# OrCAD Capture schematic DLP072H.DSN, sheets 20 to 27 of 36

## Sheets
20 PAGE25 - RS-232, SSP, USB: size A3
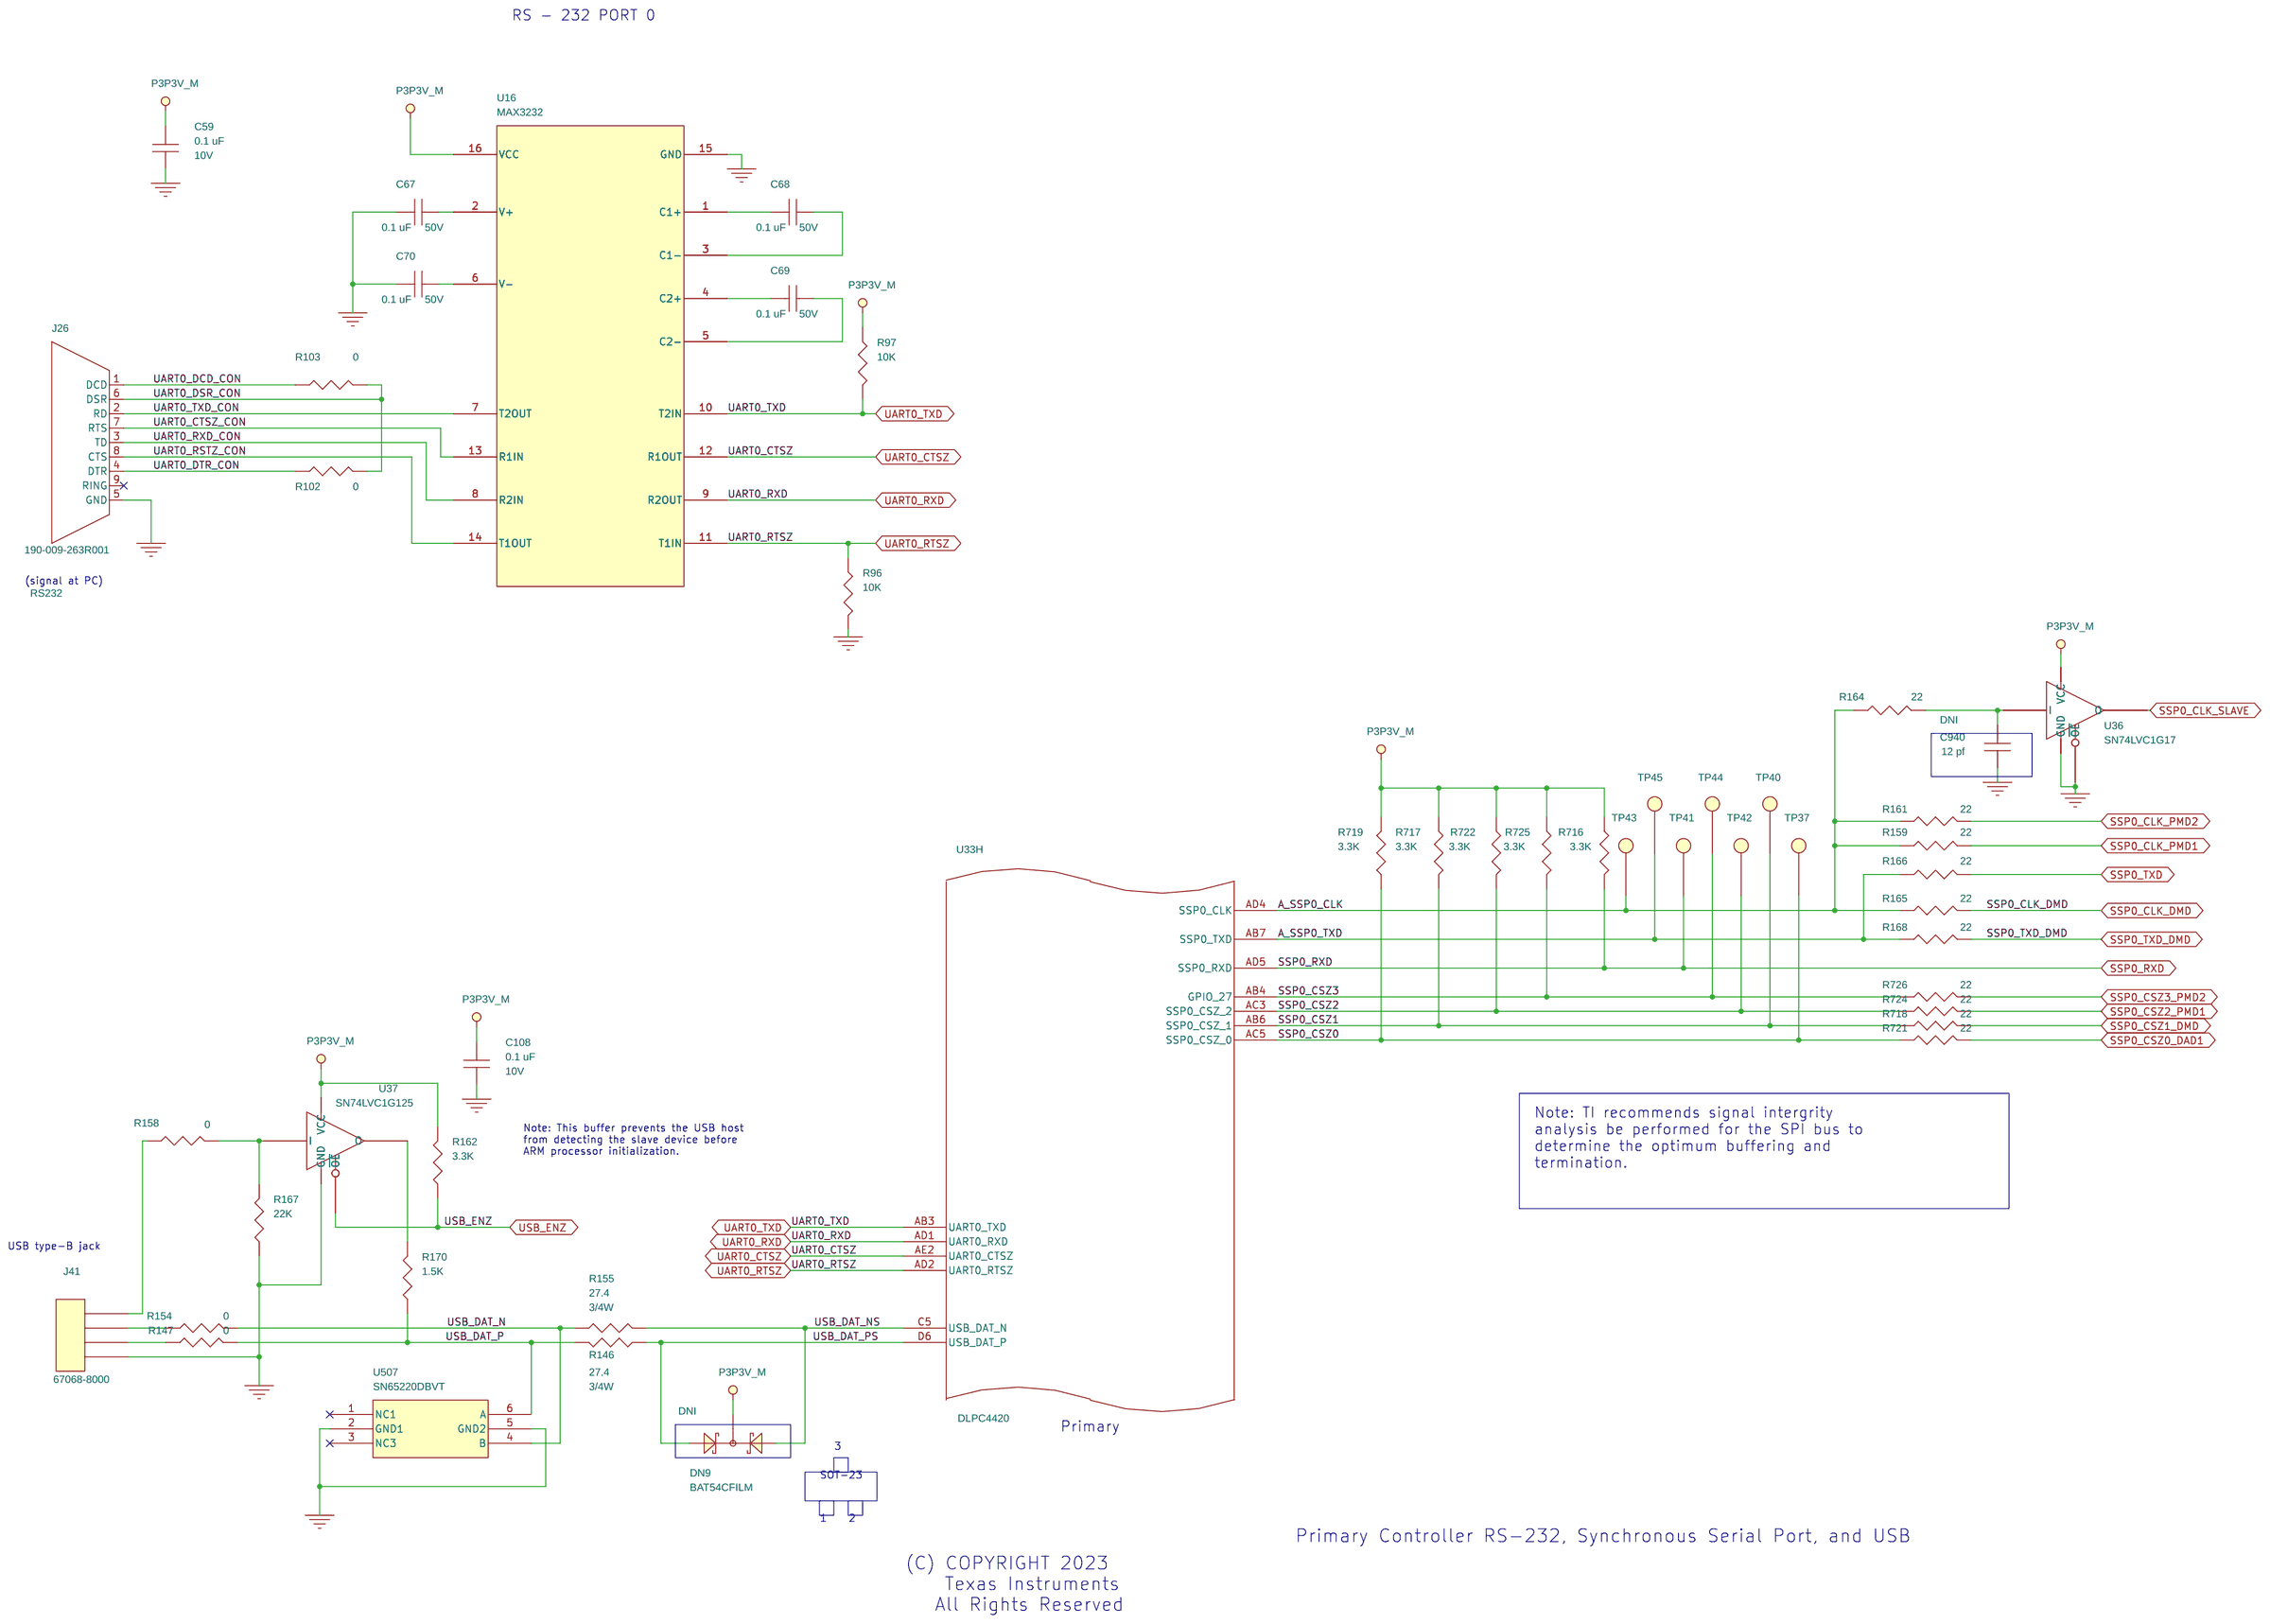
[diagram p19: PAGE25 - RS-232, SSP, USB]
21 PAGE26 - FLASH & SRAM MEMORY: size A3
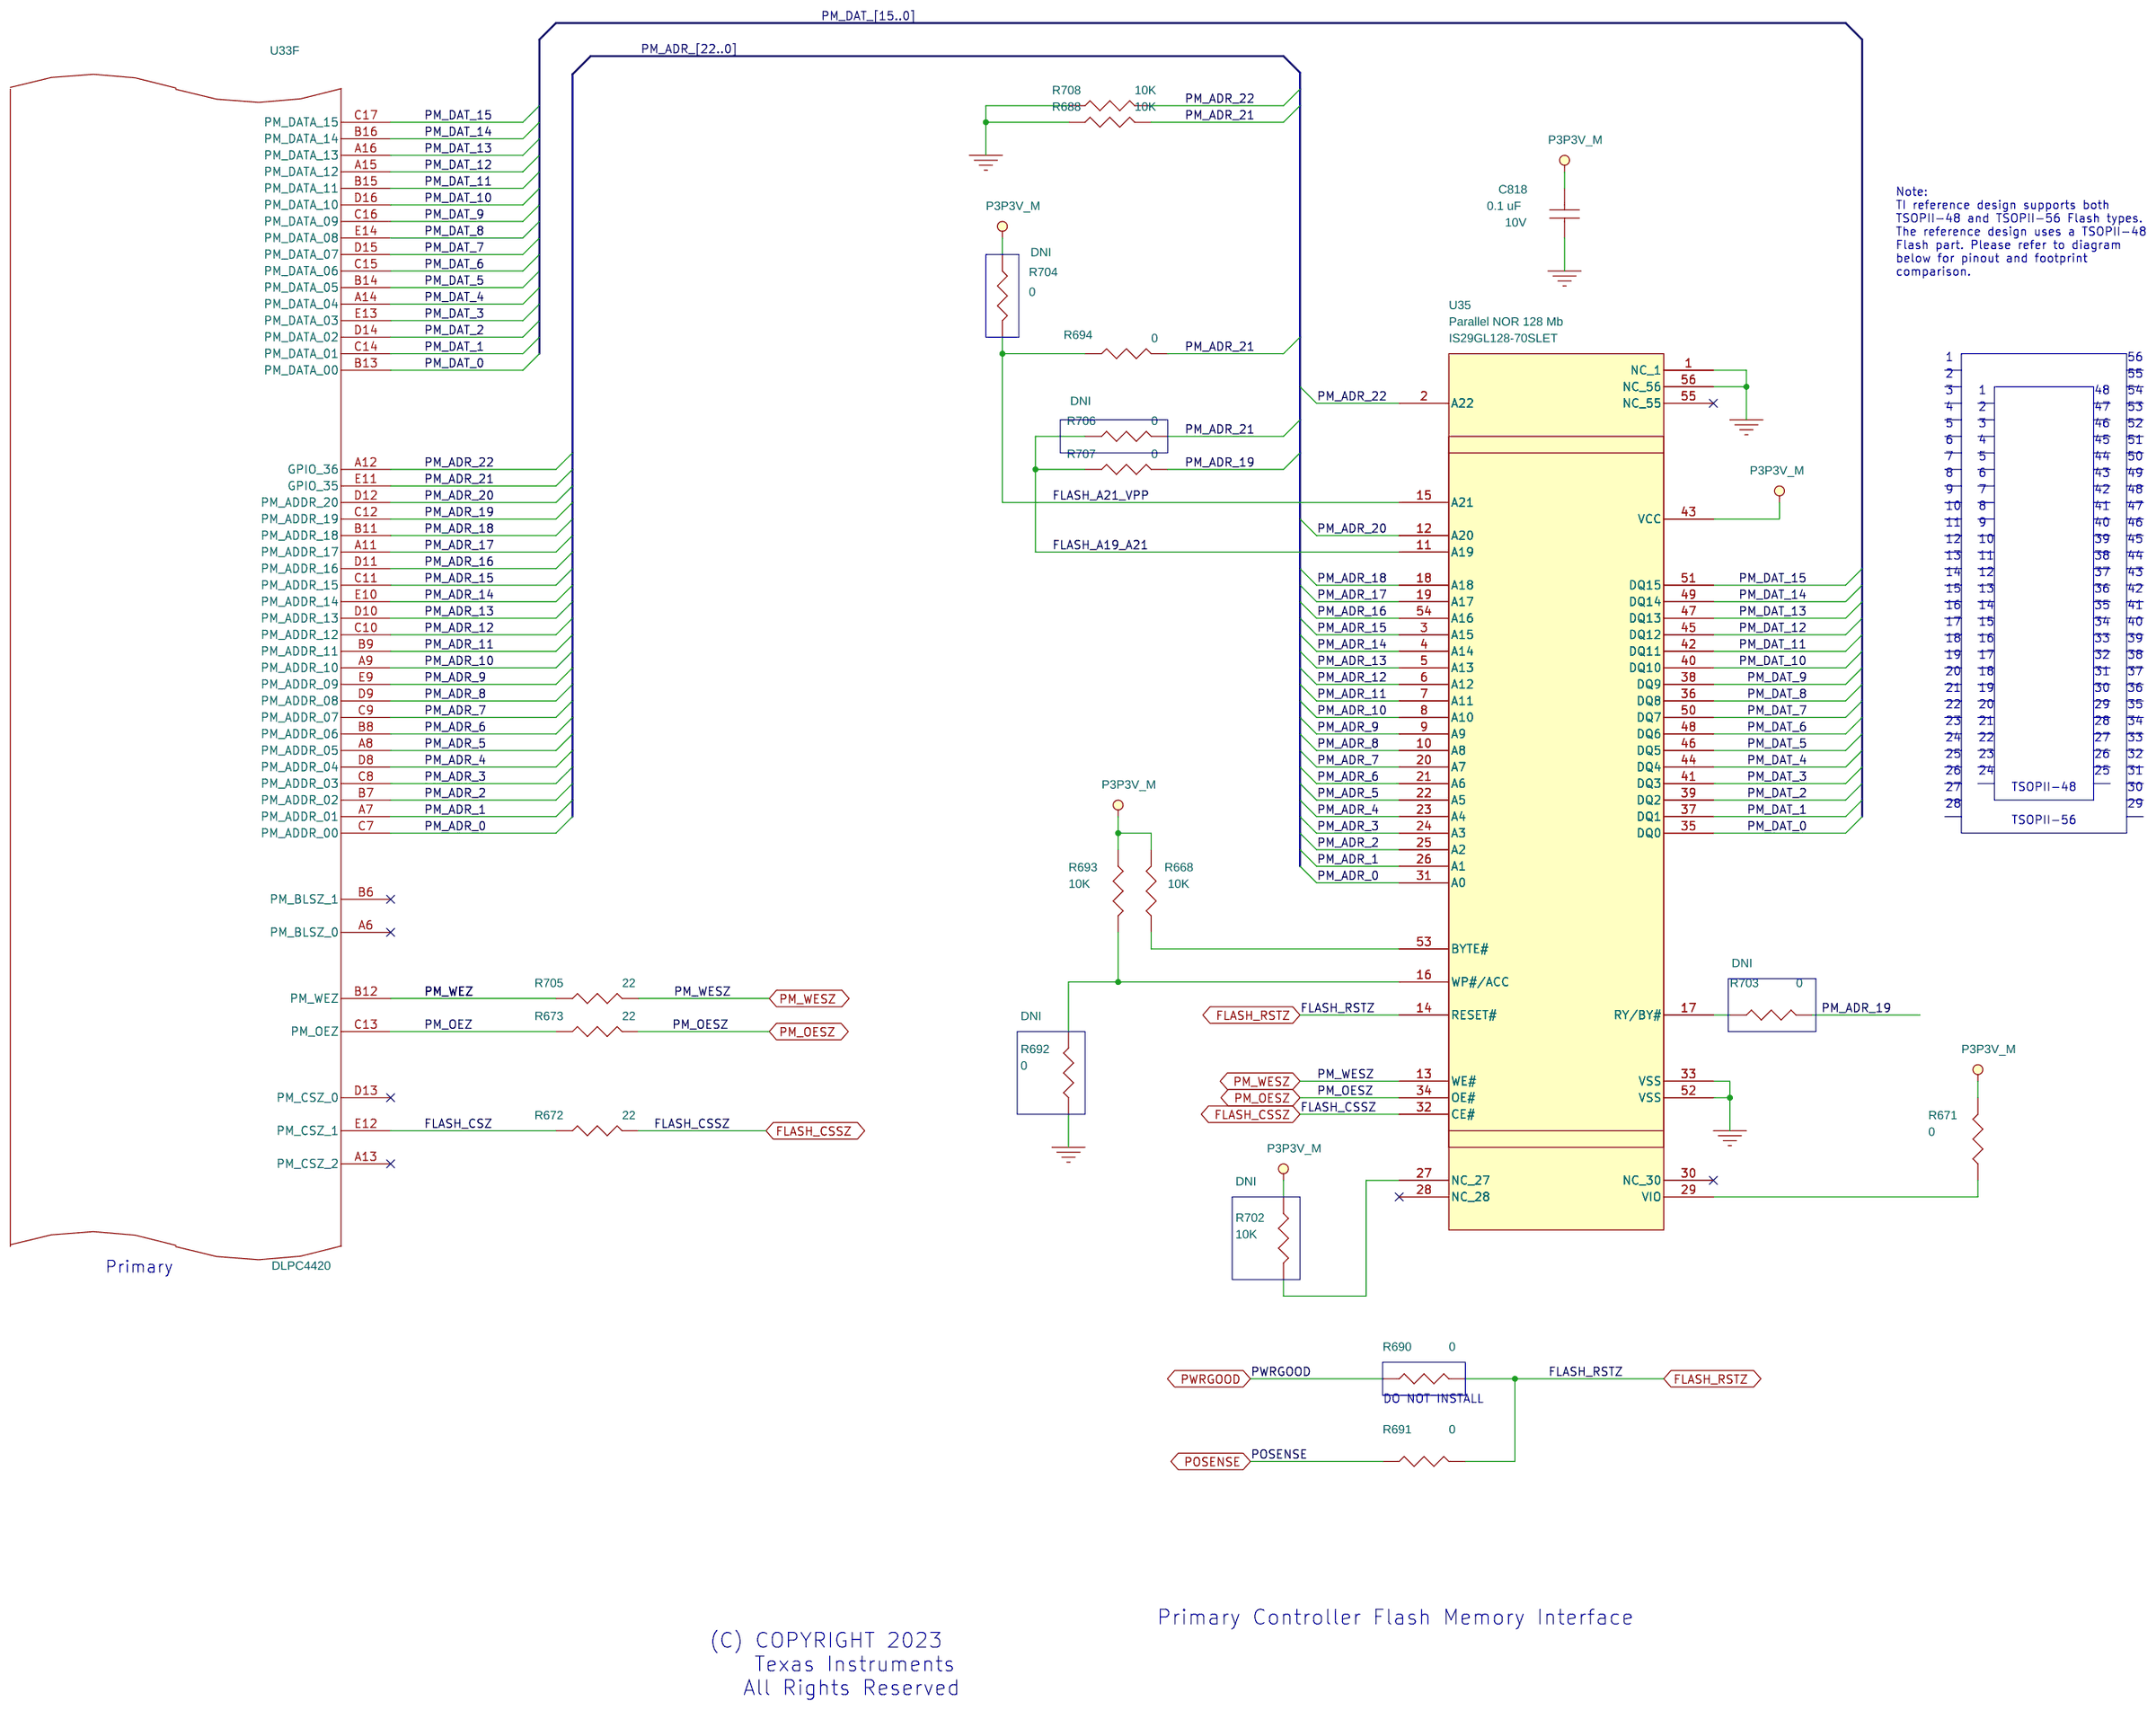
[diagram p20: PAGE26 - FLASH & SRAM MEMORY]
22 PAGE27 - SECONDARY FLASH MEMORY: size A3
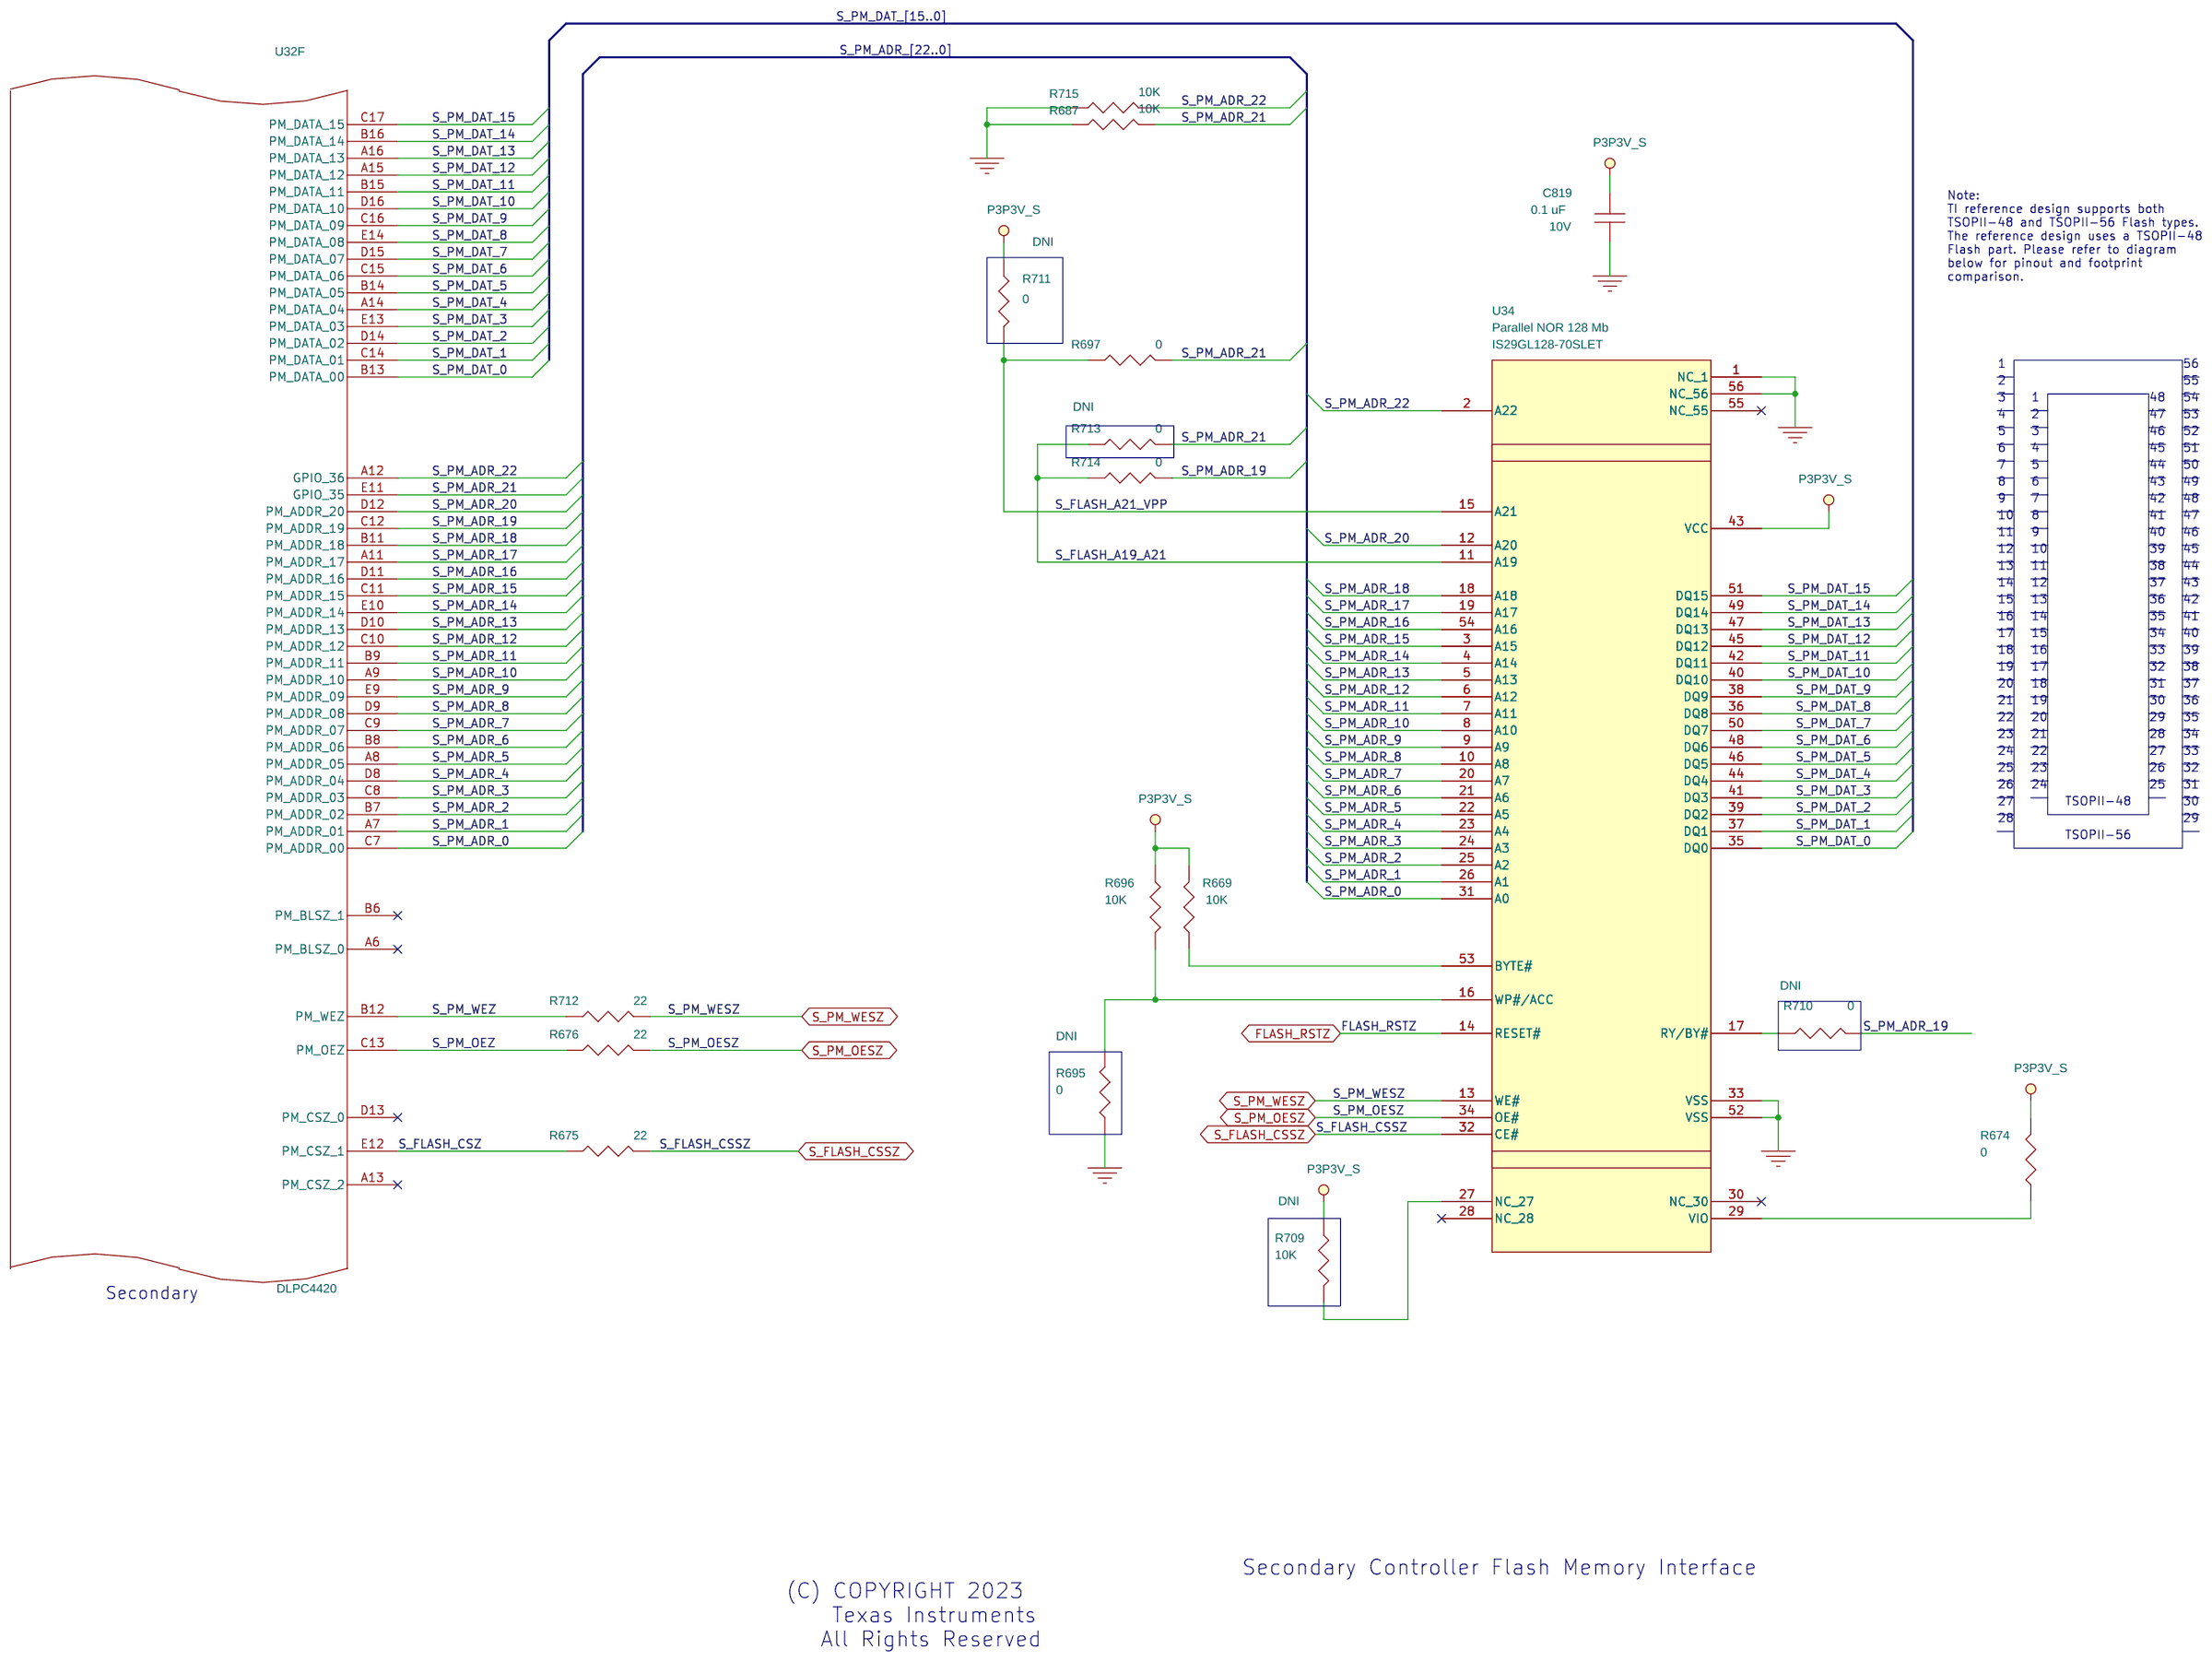
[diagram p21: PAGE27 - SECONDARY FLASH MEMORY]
23 PAGE28 - PRIMARY SSI INTERFACE: size A3
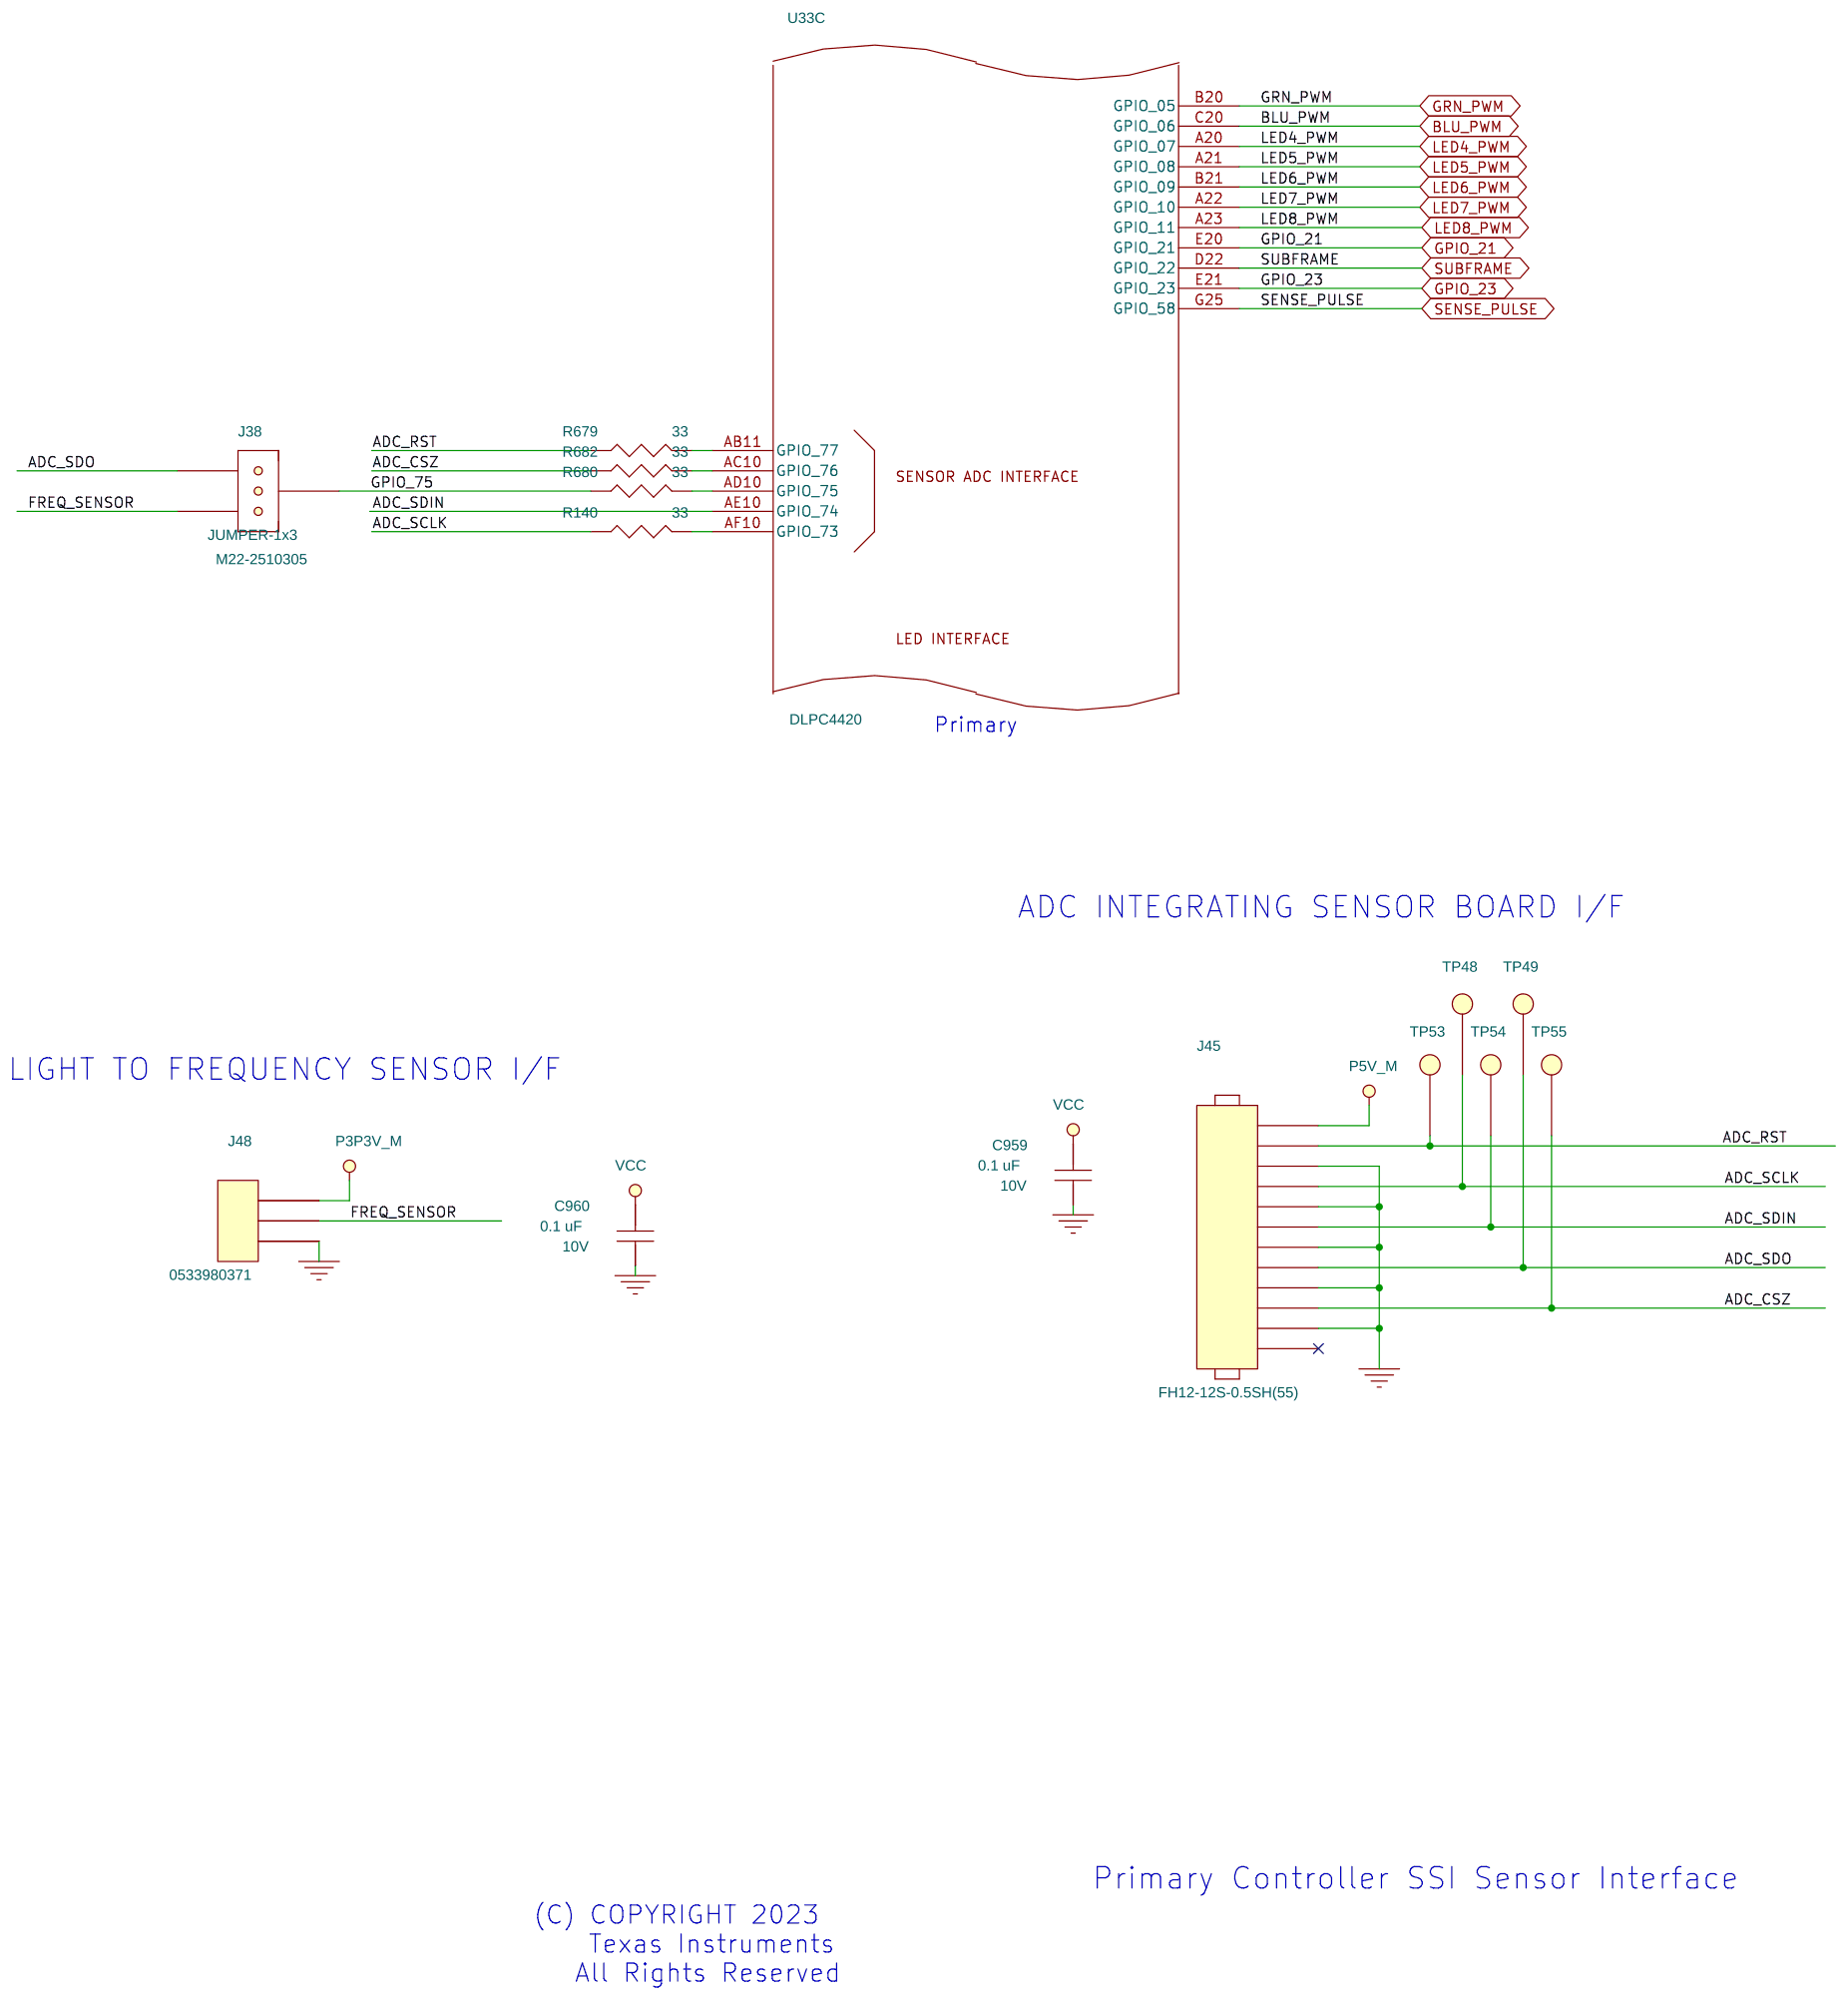
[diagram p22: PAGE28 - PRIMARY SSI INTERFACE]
24 PAGE29 - SSI DRIVER INTERFACES: size A3
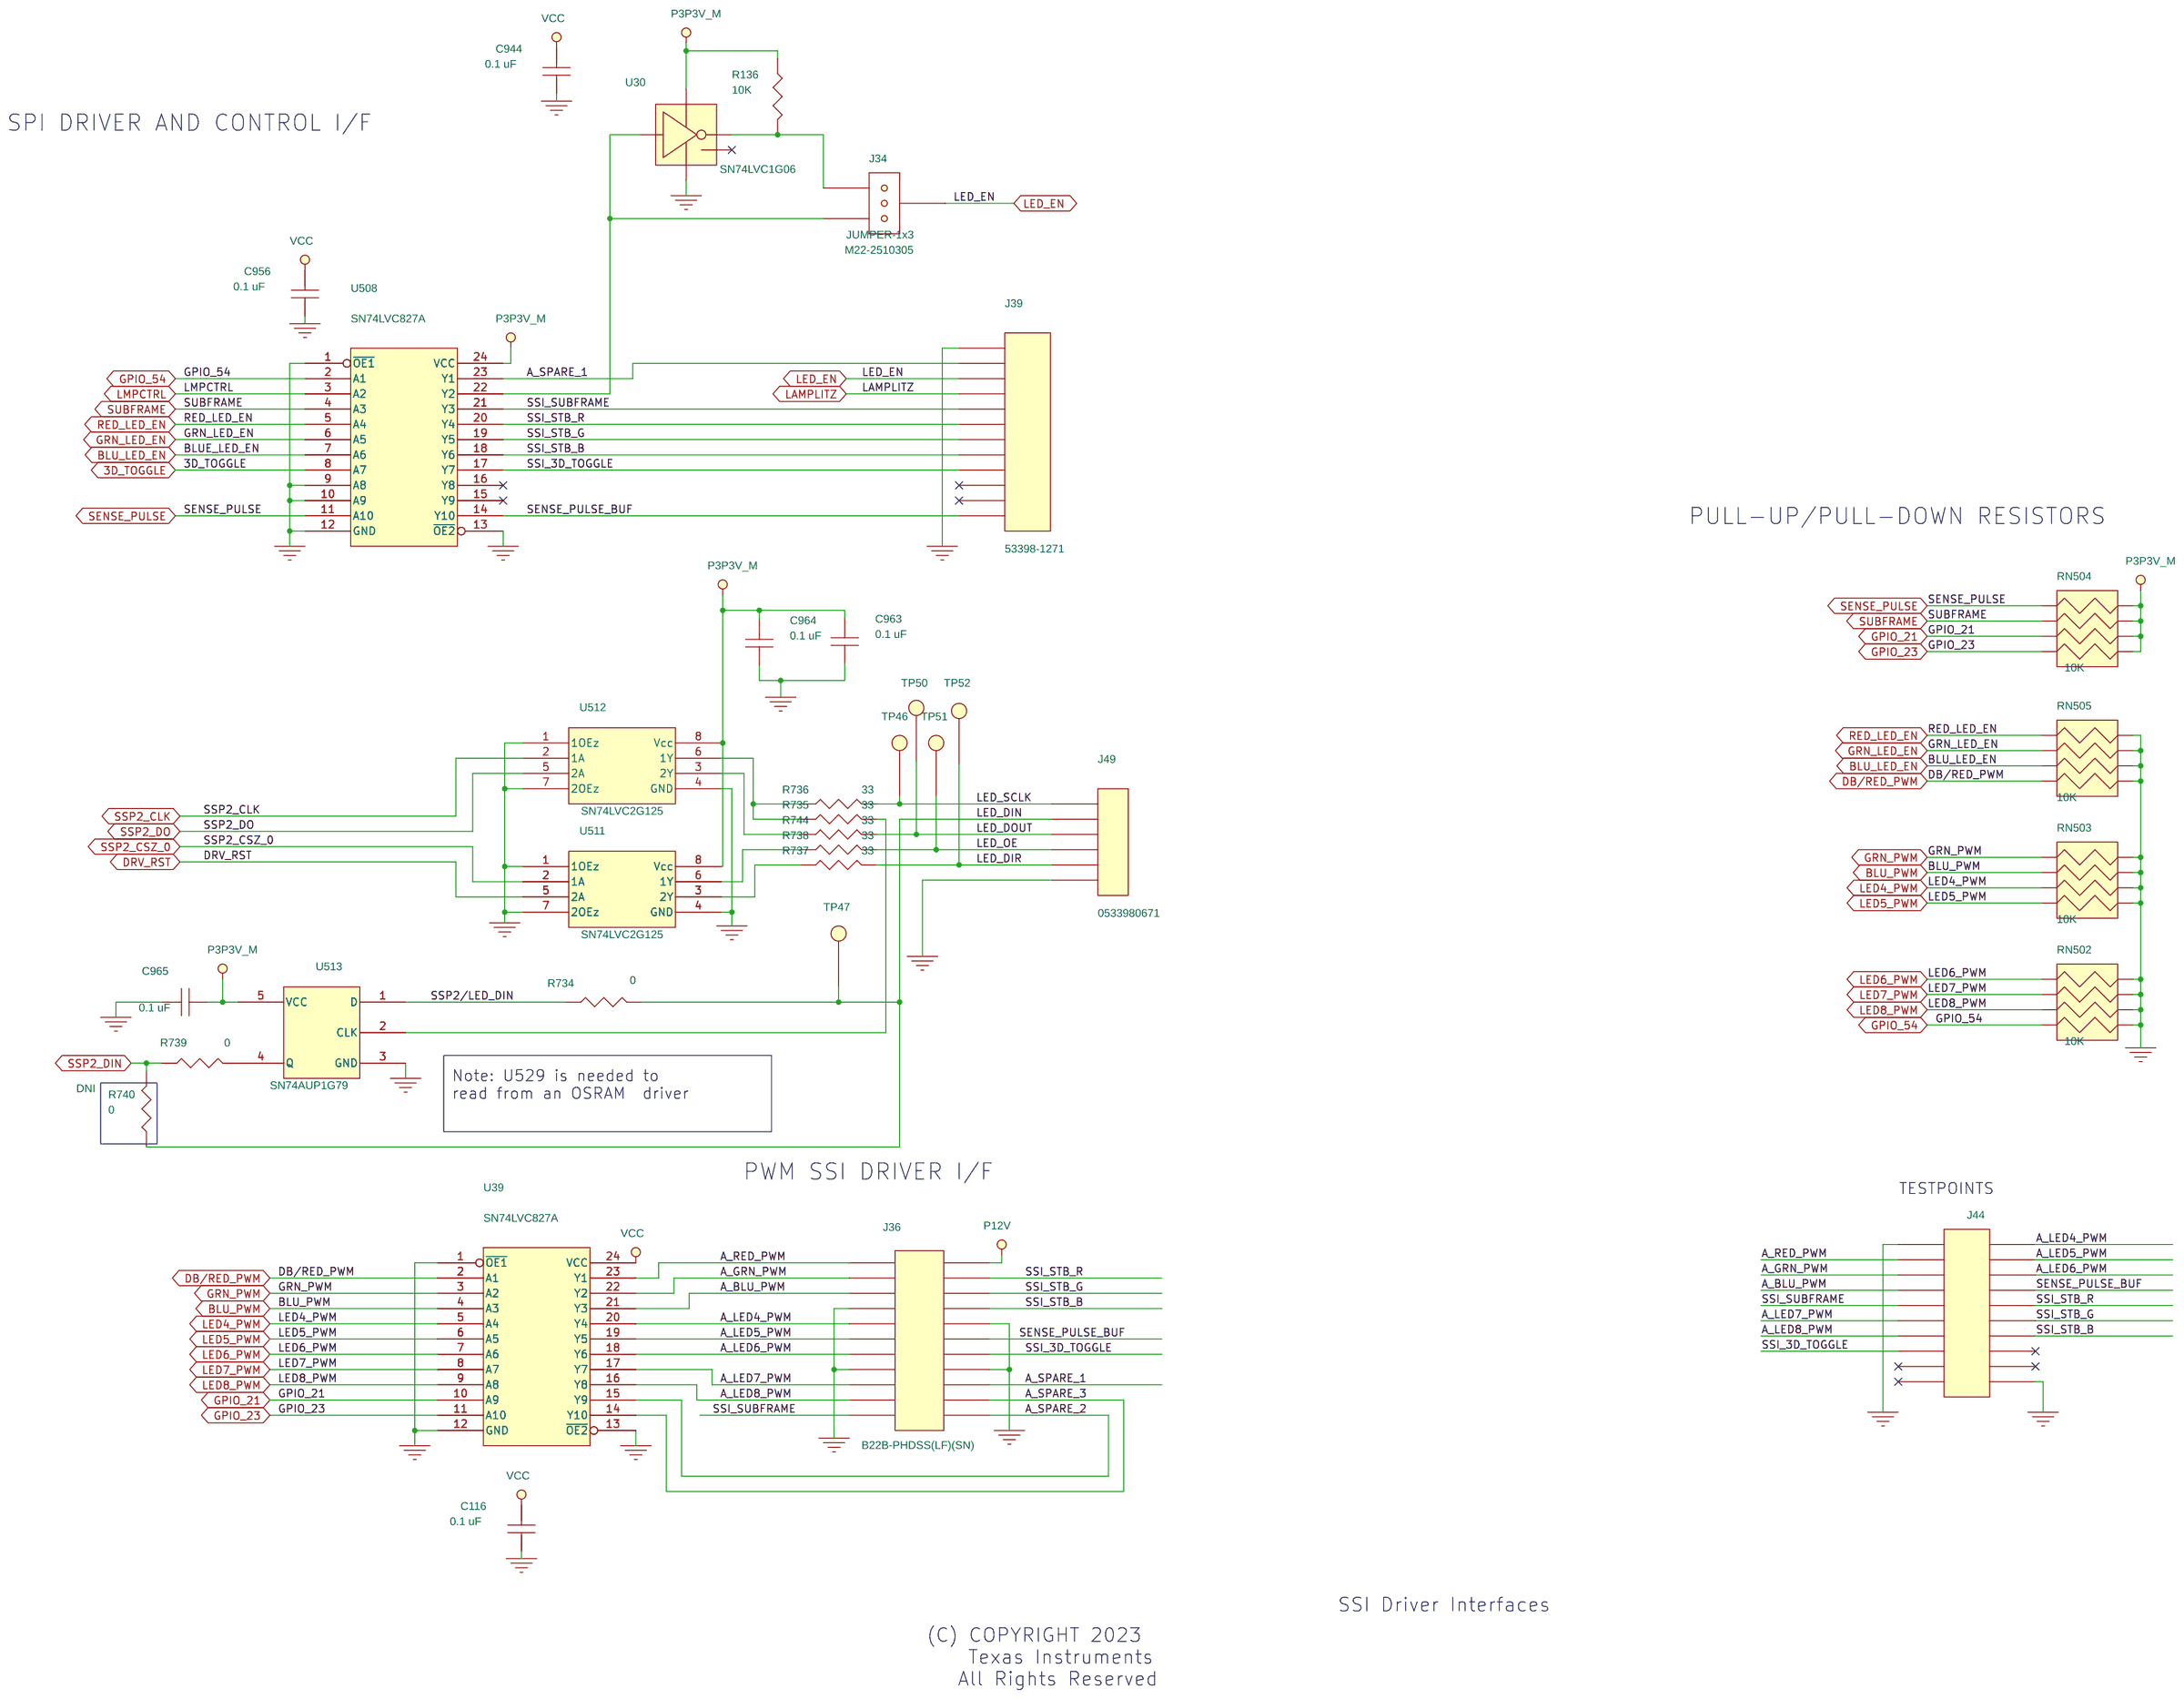
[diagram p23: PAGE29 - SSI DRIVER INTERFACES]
25 PAGE30 - SECONDARY CONTROLLER: size A3
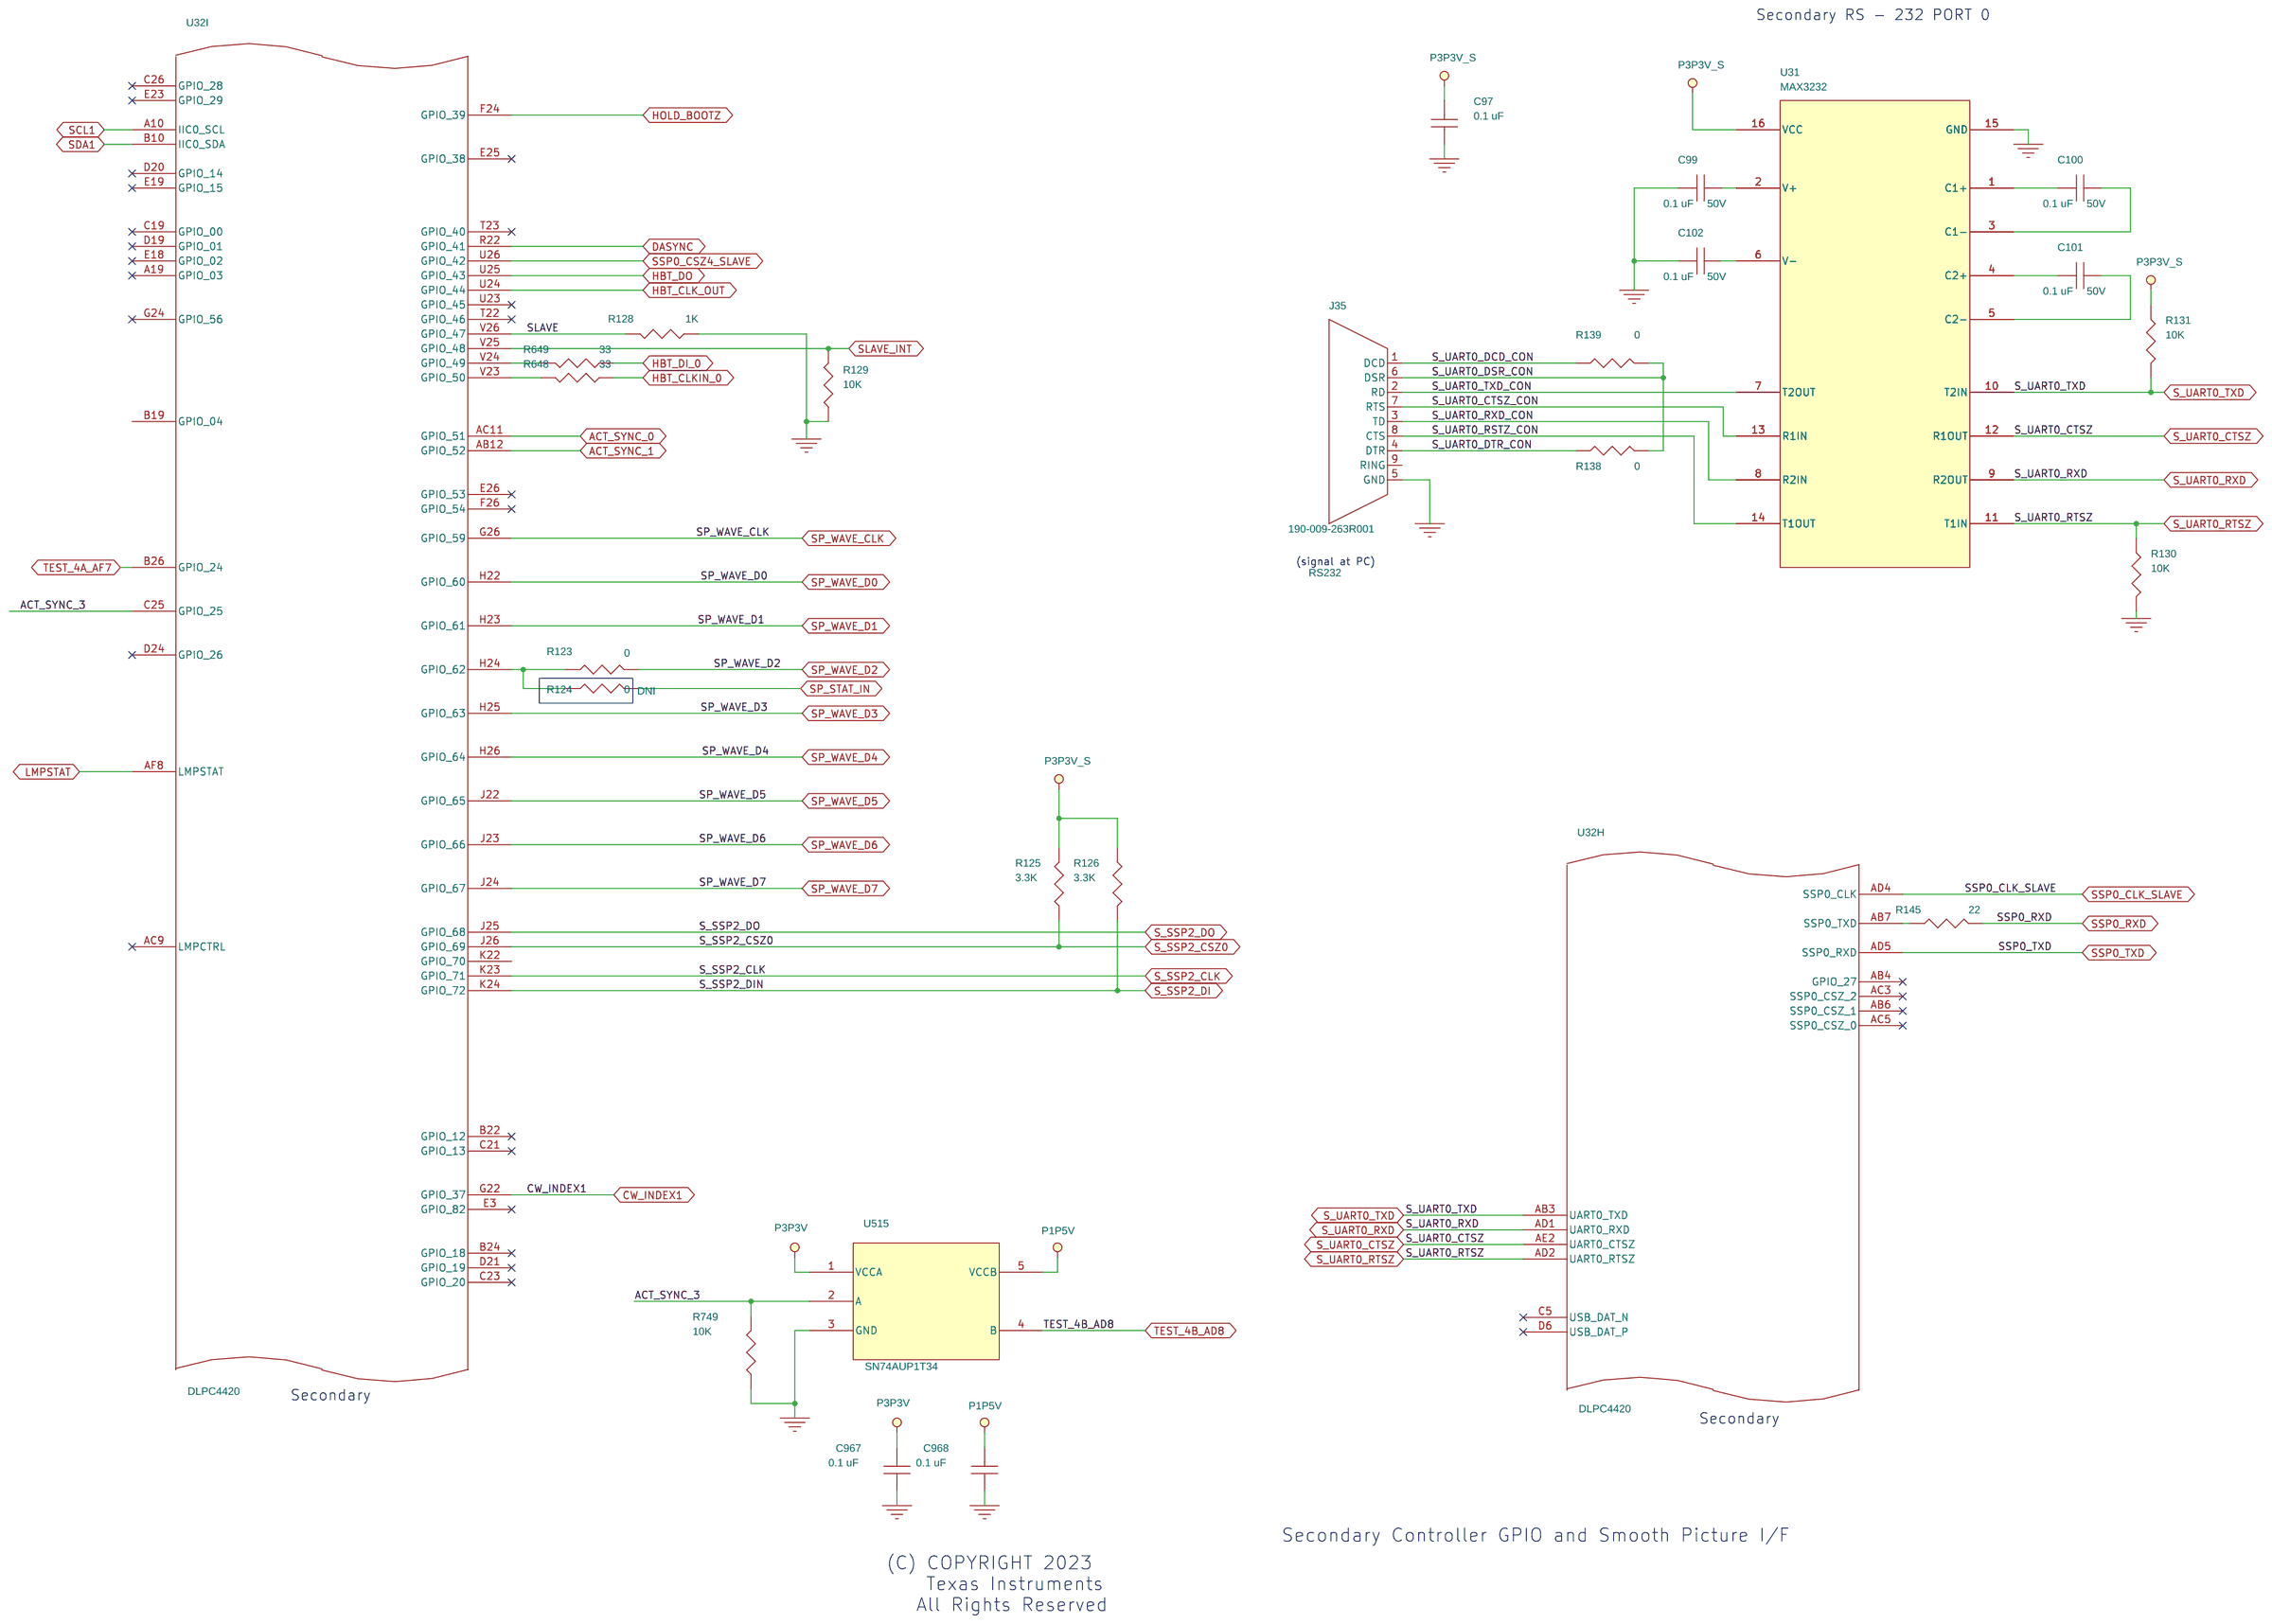
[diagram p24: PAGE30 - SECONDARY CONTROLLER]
26 PAGE31 - SMOOTH PICTURE: size A3
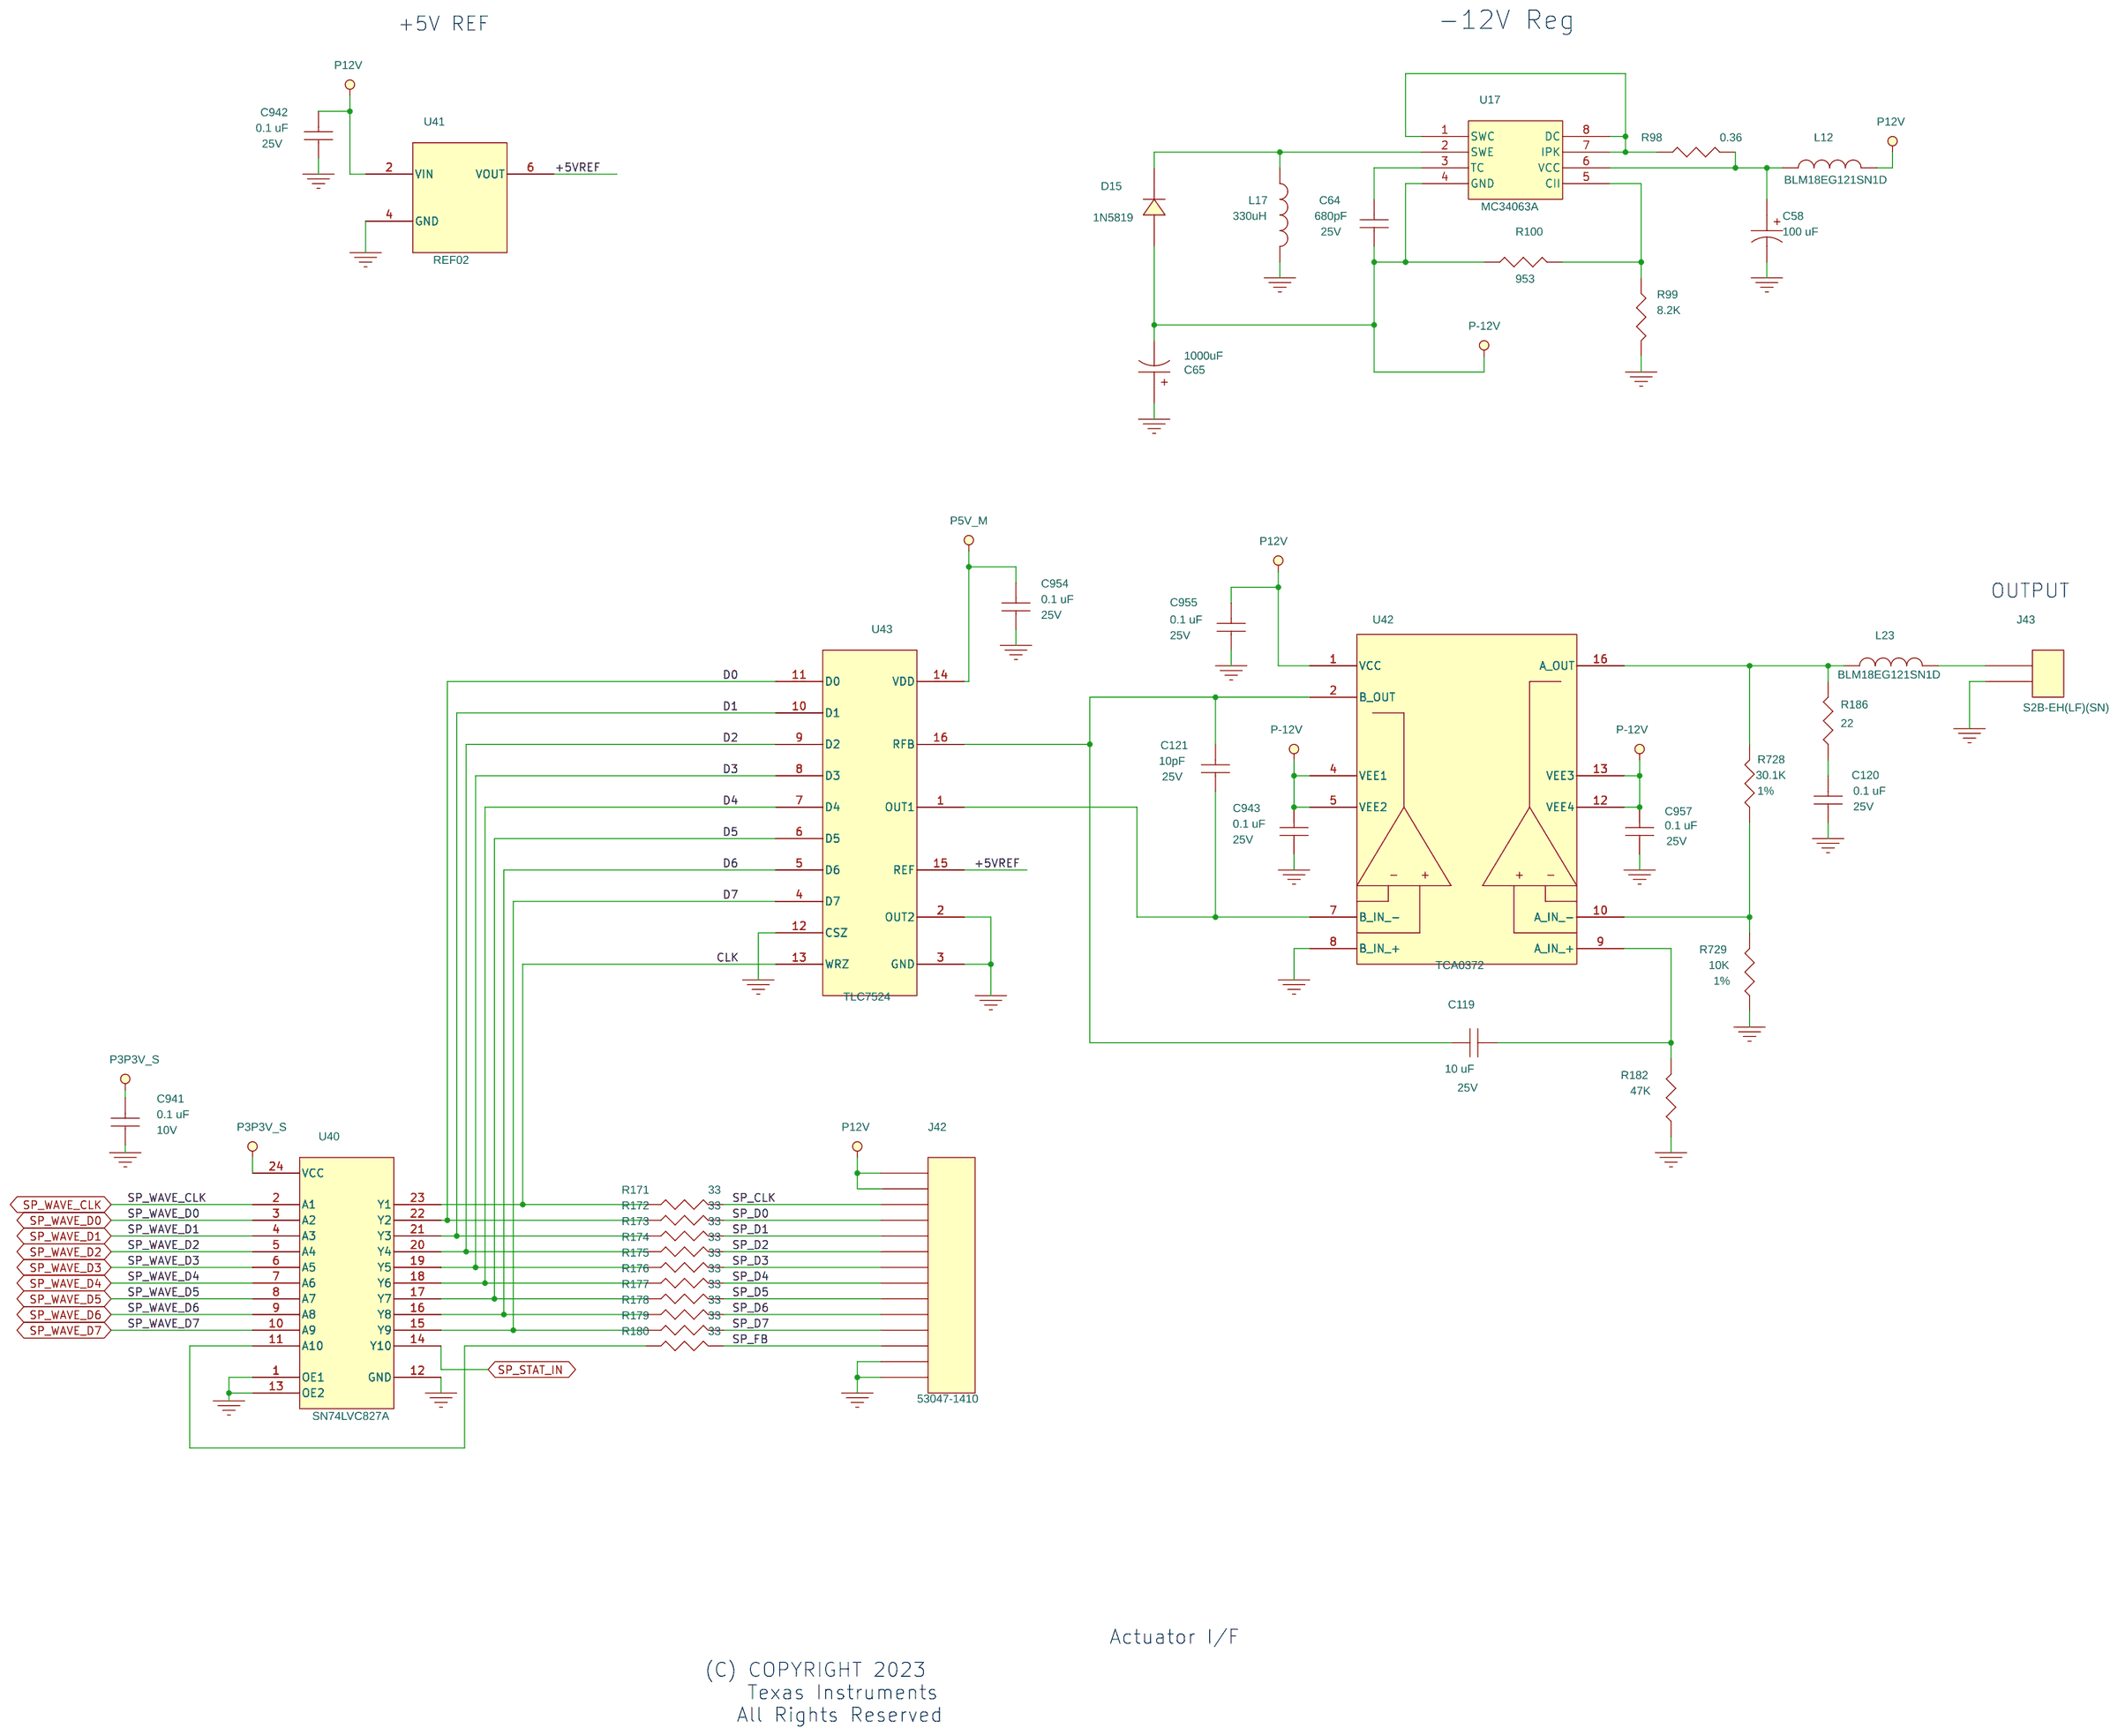
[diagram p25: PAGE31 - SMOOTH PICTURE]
27 PAGE32 - POWER & BYPASS CAPS: size A2
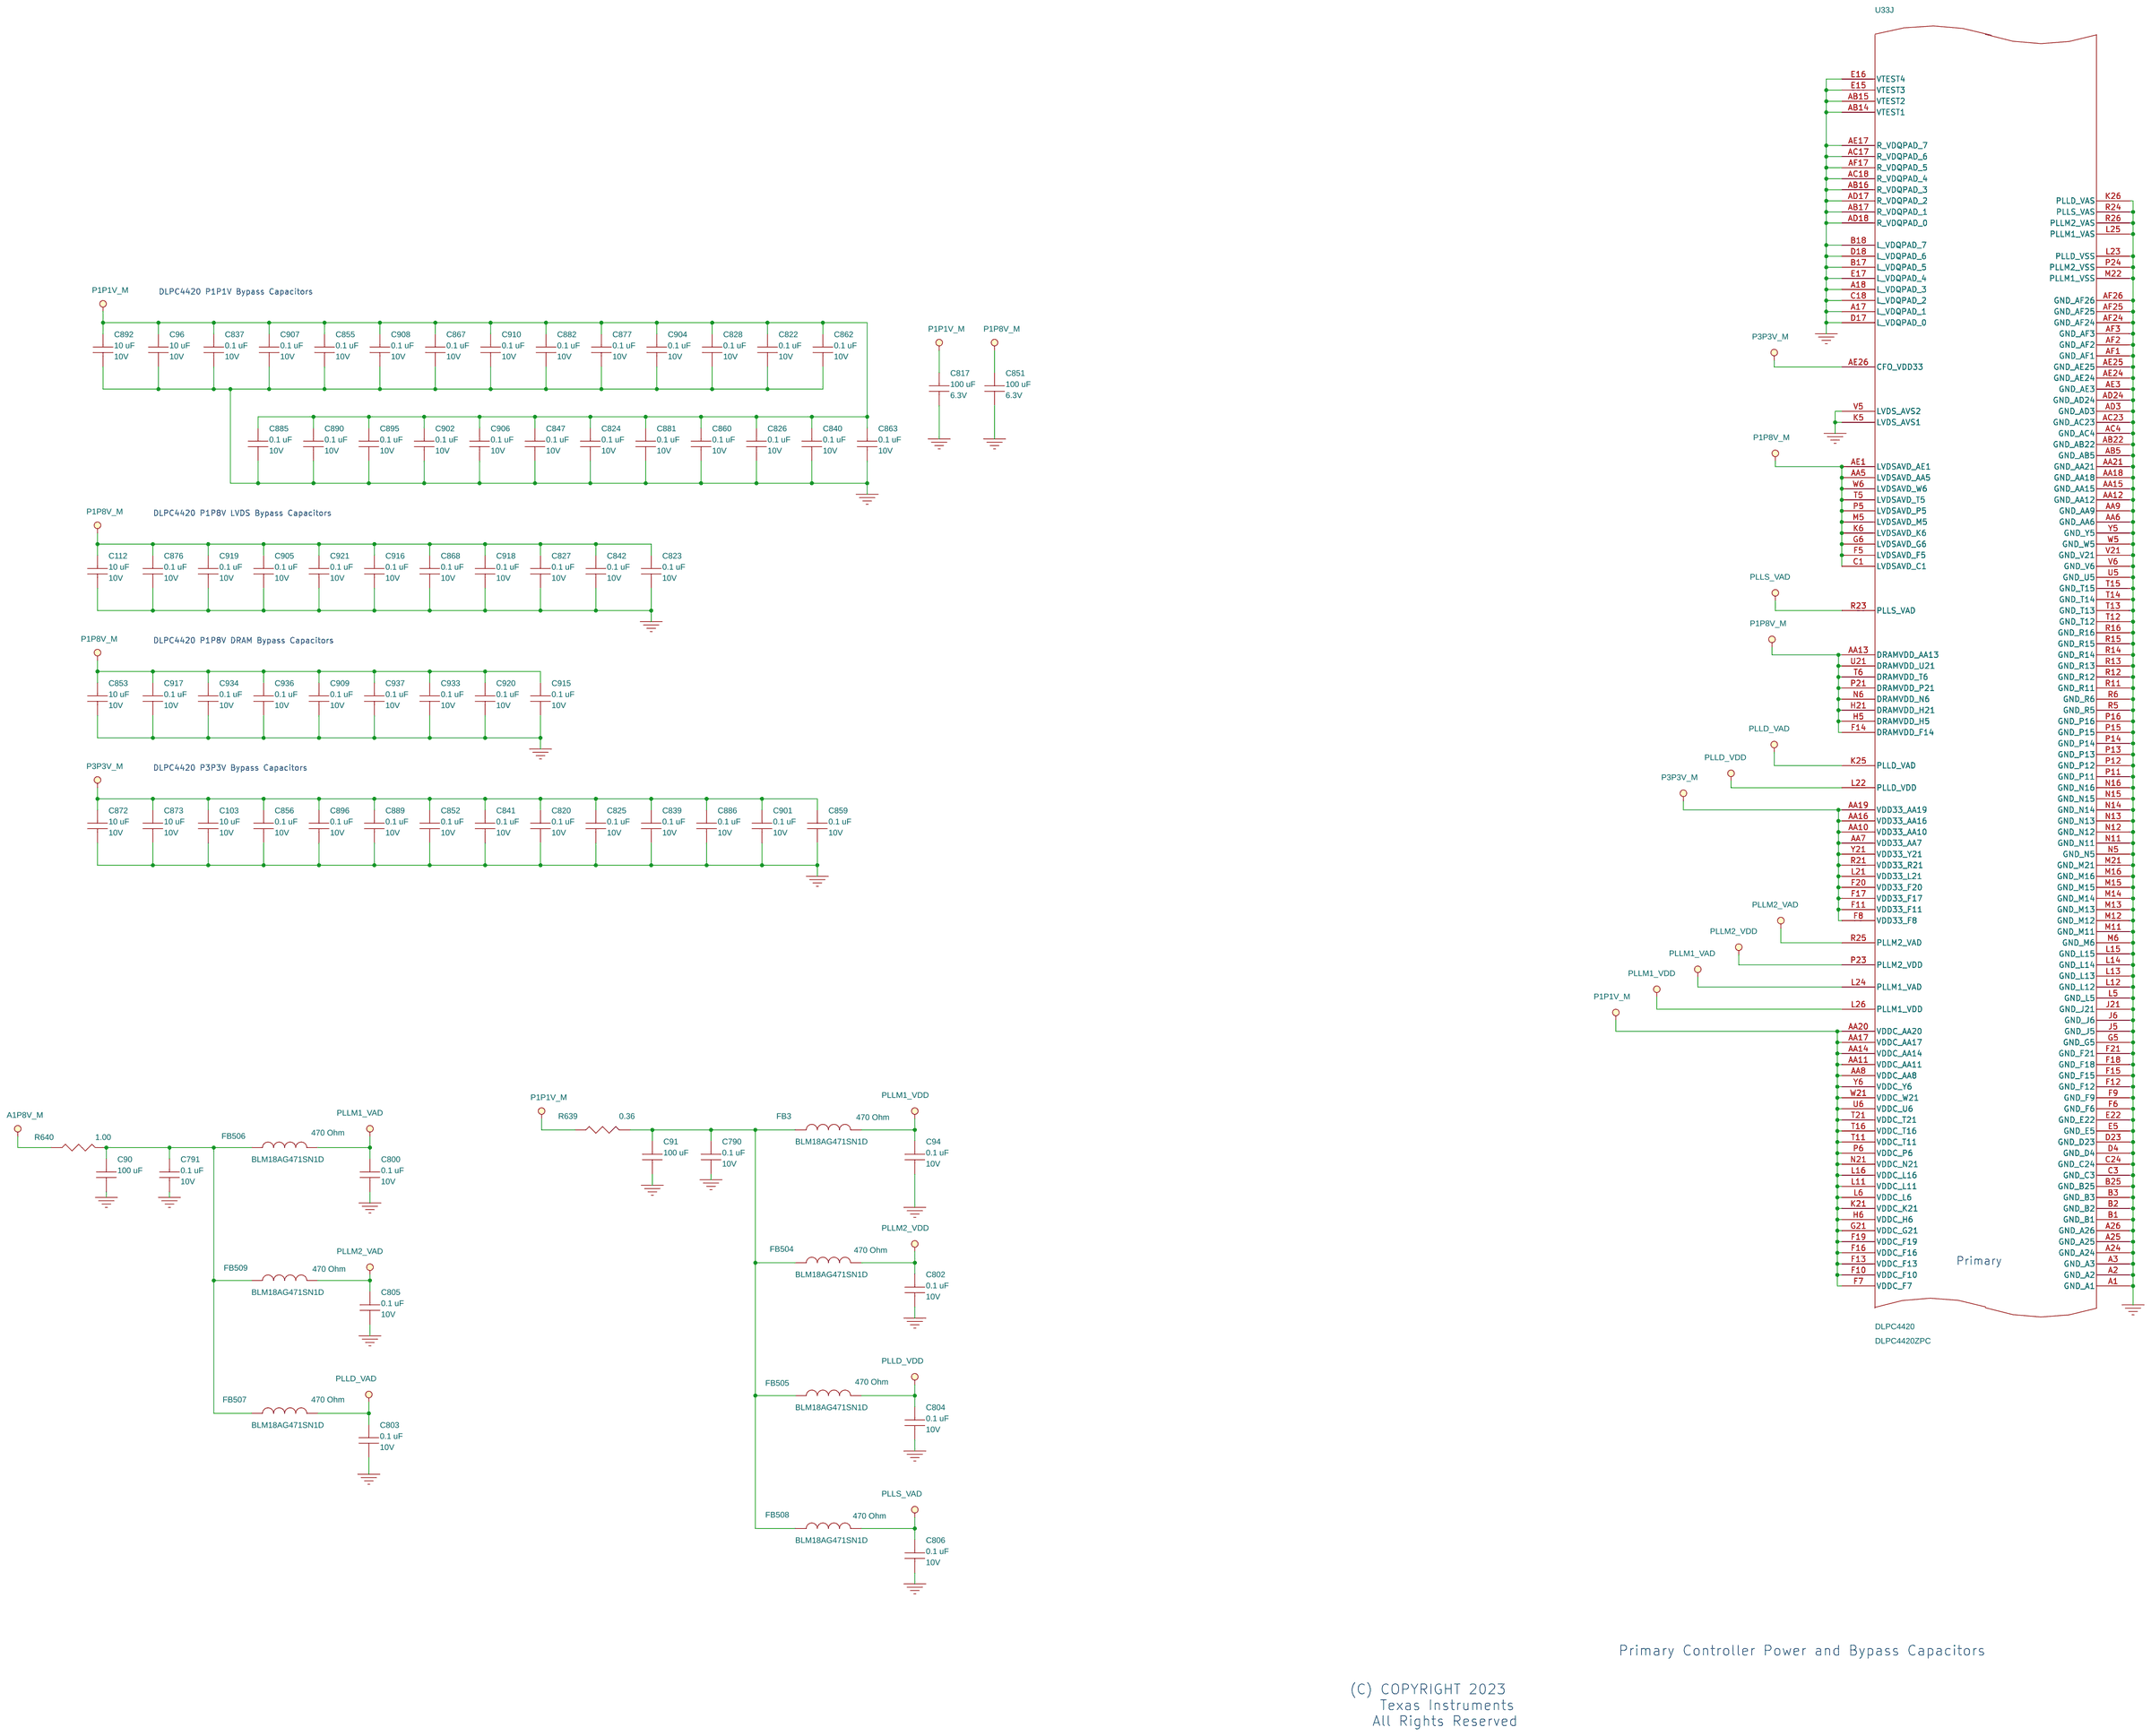
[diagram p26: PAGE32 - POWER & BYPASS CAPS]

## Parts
sheet PAGE16 - INPUT PWR & PMD1000
U32  DLPC4420  [BGA552-DDP4422_TI]  (sections A,B,C,D,E,F,G,H,I,J)
U33  DLPC4420  [BGA552-DDP4422_TI]  (sections A,B,C,D,E,F,G,H,I,J)
sheet PAGE25 - RS-232, SSP, USB
C59  0.1 uF  [CAP_0402]
C67  0.1 uF  [CAP_0805]
C68  0.1 uF  [CAP_0805]
C69  0.1 uF  [CAP_0805]
C70  0.1 uF  [CAP_0805]
C108  0.1 uF  [CAP_0402]
C940  12 pf  [CAP_0402]
DN9  BAT54C  [SOT23AVXC]
J26  RS232  [KYCON-CN9SMTA]
J41  CON4  [CONN4-67068-1000_MOLEX]
R96  10K  [RES_0402]
R97  10K  [RES_0402]
R102  0  [RES_0402]
R103  0  [RES_0402]
R146  27.4  [RES_2010]
R147  0  [RES_0402]
R154  0  [RES_0402]
R155  27.4  [RES_2010]
R158  0  [RES_0402]
R159  22  [RES_0402]
R161  22  [RES_0402]
R162  3.3K  [RES_0402]
R164  22  [RES_0402]
R165  22  [RES_0402]
R166  22  [RES_0402]
R167  22K  [RES_0603]
R168  22  [RES_0402]
R170  1.5K  [RES_0603]
R716  3.3K  [RES_0402]
R717  3.3K  [RES_0402]
R718  22  [RES_0402]
R719  3.3K  [RES_0402]
R721  22  [RES_0402]
R722  3.3K  [RES_0402]
R724  22  [RES_0402]
R725  3.3K  [RES_0402]
R726  22  [RES_0402]
TP37  Testpoint  [TP]
TP40  Testpoint  [TP]
TP41  Testpoint  [TP]
TP42  Testpoint  [TP]
TP43  Testpoint  [TP]
TP44  Testpoint  [TP]
TP45  Testpoint  [TP]
U16  MAX3232  [SOIC16-PW_TI]
U36  SN74LVC1G17  [SOT23-DBV_TI]
U37  SN74LVC1G125  [SOT23-DBV_TI]
U507  SN65220  [SOIC6-DBV_TI]
sheet PAGE26 - FLASH & SRAM MEMORY
C818  0.1 uF  [CAP_0402]
R668  10K  [RES_0402]
R671  0  [RES_0402]
R672  22  [RES_0402]
R673  22  [RES_0402]
R688  10K  [RES_0402]
R690  0  [RES_0402]
R691  0  [RES_0402]
R692  0  [RES_0402]
R693  10K  [RES_0402]
R694  0  [RES_0402]
R702  10K  [RES_0402]
R703  0  [RES_0402]
R704  0  [RES_0402]
R705  22  [RES_0402]
R706  0  [RES_0402]
R707  0  [RES_0402]
R708  10K  [RES_0402]
U35  Parallel NOR 128 Mb  [TSOP_56_48_DUAL_SKT]
sheet PAGE27 - SECONDARY FLASH MEMORY
C819  0.1 uF  [CAP_0402]
R669  10K  [RES_0402]
R674  0  [RES_0402]
R675  22  [RES_0402]
R676  22  [RES_0402]
R687  10K  [RES_0402]
R695  0  [RES_0402]
R696  10K  [RES_0402]
R697  0  [RES_0402]
R709  10K  [RES_0402]
R710  0  [RES_0402]
R711  0  [RES_0402]
R712  22  [RES_0402]
R713  0  [RES_0402]
R714  0  [RES_0402]
R715  10K  [RES_0402]
U34  Parallel NOR 128 Mb  [TSOP_56_48_DUAL_SKT]
sheet PAGE28 - PRIMARY SSI INTERFACE
C959  0.1 uF  [CAP_0402]
C960  0.1 uF  [CAP_0402]
J38  JUMPER-1x3  [HDR1X3-TMM1030X-X-S_SAM]
J45  12 HEADER  [CONN12-FH12_HRS]
J48  CON3  [CN3_53398_MOLEX]
R140  33  [RES_0402]
R679  33  [RES_0402]
R680  33  [RES_0402]
R682  33  [RES_0402]
TP48  Testpoint  [TP]
TP49  Testpoint  [TP]
TP53  Testpoint  [TP]
TP54  Testpoint  [TP]
TP55  Testpoint  [TP]
sheet PAGE29 - SSI DRIVER INTERFACES
C116  0.1 uF  [CAP_0402]
C944  0.1 uF  [CAP_0402]
C956  0.1 uF  [CAP_0402]
C963  0.1 uF  [CAP_0402]
C964  0.1 uF  [CAP_0402]
C965  0.1 uF  [CAP_0402]
J34  JUMPER-1x3  [HDR1X3-TMM1030X-X-S_SAM]
J36  CON22  [CONN22-B22B-PHD_JST]
J39  CON12  [CONN12-53398_MOLEX]
J44  CON20A  [CONN20-TSM110-0-X-DV-A_SAMTEC]
J49  CON6  [CONN6-53398-0690_MOLEX]
R136  10K  [RES_0402]
R734  0  [RES_0402]
R735  33  [RES_0402]
R736  33  [RES_0402]
R737  33  [RES_0402]
R738  33  [RES_0402]
R739  0  [RES_0402]
R740  0  [RES_0402]
R744  33  [RES_0402]
RN502  10K  [RNET8-EXB38V_PAN]
RN503  10K  [RNET8-EXB38V_PAN]
RN504  10K  [RNET8-EXB38V_PAN]
RN505  10K  [RNET8-EXB38V_PAN]
TP46  Testpoint  [TP]
TP47  Testpoint  [TP]
TP50  Testpoint  [TP]
TP51  Testpoint  [TP]
TP52  Testpoint  [TP]
U30  SN74LVC1G06  [SOIC5-DBV_TI]
U39  SN74LVC827A  [SOIC24-PW_TI]
U508  SN74LVC827A  [SOIC24-PW_TI]
U511  SN74LVC2G125  [8US8]
U512  SN74LVC2G125  [8US8]
U513  SN74AUP1G79  [SOT23-5]
sheet PAGE30 - SECONDARY CONTROLLER
C97  0.1 uF  [CAP_0402]
C99  0.1 uF  [CAP_0805]
C100  0.1 uF  [CAP_0805]
C101  0.1 uF  [CAP_0805]
C102  0.1 uF  [CAP_0805]
C967  0.1 uF  [CAP_0402]
C968  0.1 uF  [CAP_0402]
J35  RS232  [KYCON-CN9SMTA]
R123  0  [RES_0402]
R124  0  [RES_0402]
R125  3.3K  [RES_0402]
R126  3.3K  [RES_0402]
R128  1K  [RES_0402]
R129  10K  [RES_0402]
R130  10K  [RES_0402]
R131  10K  [RES_0402]
R138  0  [RES_0402]
R139  0  [RES_0402]
R145  22  [RES_0402]
R648  33  [RES_0402]
R649  33  [RES_0402]
R749  10K  [RES_0402]
U31  MAX3232  [SOIC16-PW_TI]
U515  SN74AUP1T34  [SC70-5]
sheet PAGE31 - SMOOTH PICTURE
C58  100 uF  [CAP-FK-V-CASEE_PAN]
C64  680pF  [CAP_0603]
C65  1000uF  [VK_10mm]
C119  10 uF  [CAP_0805]
C120  0.1 uF  [CAP_0603]
C121  10pF  [CAP_0603]
C941  0.1 uF  [CAP_0402]
C942  0.1 uF  [CAP_0603]
C943  0.1 uF  [CAP_0603]
C954  0.1 uF  [CAP_0603]
C955  0.1 uF  [CAP_0603]
C957  0.1 uF  [CAP_0603]
D15  1N5819  [SOD123]
J42  CON14  [CONN14-53047_MLX]
J43  S2B-EH(LF)(SN)  [CN2_2_5MM]
L12  120 Ohm  [IND_0603]
L17  330uH  [IND_SRR1210]
L23  120 Ohm  [IND_0603]
R98  0.36  [RES_0402]
R99  8.2K  [RES_0603]
R100  953  [RES_0603]
R171  33  [RES_0402]
R172  33  [RES_0402]
R173  33  [RES_0402]
R174  33  [RES_0402]
R175  33  [RES_0402]
R176  33  [RES_0402]
R177  33  [RES_0402]
R178  33  [RES_0402]
R179  33  [RES_0402]
R180  33  [RES_0402]
R182  47K  [RES_0603]
R186  22  [RES_0402]
R728  30.1K  [RES_0603]
R729  10K  [RES_0402]
U17  MC34063A  [SOIC8]
U40  SN74LVC827A  [SOIC24-PW_TI]
U41  REF02  [SOIC8]
U42  TCA0372  [16-SOIC]
U43  TLC7524  [TSSOP16]
sheet PAGE32 - POWER & BYPASS CAPS
C90  100 uF  [CAP_1206]
C91  100 uF  [CAP_1206]
C94  0.1 uF  [CAP_0402]
C96  10 uF  [CAP_0805]
C103  10 uF  [CAP_0805]
C112  10 uF  [CAP_0805]
C790  0.1 uF  [CAP_0402]
C791  0.1 uF  [CAP_0402]
C800  0.1 uF  [CAP_0402]
C802  0.1 uF  [CAP_0402]
C803  0.1 uF  [CAP_0402]
C804  0.1 uF  [CAP_0402]
C805  0.1 uF  [CAP_0402]
C806  0.1 uF  [CAP_0402]
C817  100 uF  [CAP_1206]
C820  0.1 uF  [CAP_0402]
C822  0.1 uF  [CAP_0402]
C823  0.1 uF  [CAP_0402]
C824  0.1 uF  [CAP_0402]
C825  0.1 uF  [CAP_0402]
C826  0.1 uF  [CAP_0402]
C827  0.1 uF  [CAP_0402]
C828  0.1 uF  [CAP_0402]
C837  0.1 uF  [CAP_0402]
C839  0.1 uF  [CAP_0402]
C840  0.1 uF  [CAP_0402]
C841  0.1 uF  [CAP_0402]
C842  0.1 uF  [CAP_0402]
C847  0.1 uF  [CAP_0402]
C851  100 uF  [CAP_1206]
C852  0.1 uF  [CAP_0402]
C853  10 uF  [CAP_0805]
C855  0.1 uF  [CAP_0402]
C856  0.1 uF  [CAP_0402]
C859  0.1 uF  [CAP_0402]
C860  0.1 uF  [CAP_0402]
C862  0.1 uF  [CAP_0402]
C863  0.1 uF  [CAP_0402]
C867  0.1 uF  [CAP_0402]
C868  0.1 uF  [CAP_0402]
C872  10 uF  [CAP_0805]
C873  10 uF  [CAP_0805]
C876  0.1 uF  [CAP_0402]
C877  0.1 uF  [CAP_0402]
C881  0.1 uF  [CAP_0402]
C882  0.1 uF  [CAP_0402]
C885  0.1 uF  [CAP_0402]
C886  0.1 uF  [CAP_0402]
C889  0.1 uF  [CAP_0402]
C890  0.1 uF  [CAP_0402]
C892  10 uF  [CAP_0805]
C895  0.1 uF  [CAP_0402]
C896  0.1 uF  [CAP_0402]
C901  0.1 uF  [CAP_0402]
C902  0.1 uF  [CAP_0402]
C904  0.1 uF  [CAP_0402]
C905  0.1 uF  [CAP_0402]
C906  0.1 uF  [CAP_0402]
C907  0.1 uF  [CAP_0402]
C908  0.1 uF  [CAP_0402]
C909  0.1 uF  [CAP_0402]
C910  0.1 uF  [CAP_0402]
C915  0.1 uF  [CAP_0402]
C916  0.1 uF  [CAP_0402]
C917  0.1 uF  [CAP_0402]
C918  0.1 uF  [CAP_0402]
C919  0.1 uF  [CAP_0402]
C920  0.1 uF  [CAP_0402]
C921  0.1 uF  [CAP_0402]
C933  0.1 uF  [CAP_0402]
C934  0.1 uF  [CAP_0402]
C936  0.1 uF  [CAP_0402]
C937  0.1 uF  [CAP_0402]
FB3  470 Ohm  [FLTR_0603]
FB504  470 Ohm  [FLTR_0603]
FB505  470 Ohm  [FLTR_0603]
FB506  470 Ohm  [FLTR_0603]
FB507  470 Ohm  [FLTR_0603]
FB508  470 Ohm  [FLTR_0603]
FB509  470 Ohm  [FLTR_0603]
R639  0.36  [RES_0402]
R640  1.00  [RES_0402]

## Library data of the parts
U32 U33 = DDP442x: IC, ASIC; CCA: 54; MFG: TI; Part Number: DLPC4420ZPC; SOURCE: PROVIDED BY TI
C59 C94 C97 C108 C116 C790 C791 C800 C802-C806 C818-C820 C822-C828 C837 C839-C842 C847 C852 C855 C856 C859 C860 C862 C863 C867 C868 C876 C877 C881 C882 C885 C886 C889 C890 C895 C896 C901 C902 C904-C910 C915-C921 C933 C934 C936 C937 C941 C944 C956 C959 C960 C963-C965 C967 C968 = CAP_NP: Capacitor; CCA: 34; MFG: KEMET; Part Number: C0402C104K8RACTU; RATING: 10V; SOURCE: DIGI 399-3520-1-ND; TOLERANCE: 10%; Type: X7R
C67-C70 C99-C102 = CAP_NP: Capacitor; CCA: 9; MFG: AVX; Part Number: 08055C104MAT2A; RATING: 50V; SOURCE: DIGI 478-3351-1-ND; TOLERANCE: 10%; Type: X7R
C940 = CAP_NP: Capacitor; CCA: 120; DNI: DNI; MFG: Vishay Vitramon; Part Number: VJ0402A120JXACW1BC; RATING: 50V; TOLERANCE: 5%; Type: NPO
DN9 = DS_DUAL_CK_JAA_0: Diode, Schottky, Dual; CCA: 28; DNI: DNI; MFG: STMICRO; Part Number: BAT54CFILM; RATING: 30V, 300mA; SOURCE: DIGI 497-3786-2-ND
J26 J35 = RS232: Connector, 9 pin, D-Sub; CCA: 126; MFG: NORCOMP; Part Number: 190-009-263R001; SOURCE: MOUSER 806-K20XHT-E9S-N
J41 = CON4: Connector, USB type-B; CCA: 23; MFG: MOLEX; Part Number: 67068-8000; SOURCE: DIGI WM17113-ND
R96 R97 R129-R131 R136 R668 R669 R687 R688 R693 R696 R708 R715 R749 = R: Resistor; CCA: 65; ICA_MFR_NAME: PANASONIC; ICA_PARTNUM: $$1785048$$ERJ-3GSYJ102; MFG: PANASONIC; Part Number: ERJ-2GEJ103X; RATING: 1/10W; SOURCE: DIGI P10.0KLCT-ND; TOLERANCE: 5%
R102 R103 R123 R138 R139 R147 R154 R158 R671 R674 R691 R694 R697 R707 R714 R734 R739 = R: Resistor; CCA: 62; ICA_MFR_NAME: PANASONIC; ICA_PARTNUM: $$1785048$$ERJ-3GSYJ102; MFG: PANASONIC; Part Number: ERJ-2GE0R00X; RATING: 1/10W; SOURCE: DIGI P0.0JCT-ND
R146 R155 = R: Resistor; CCA: 101; ICA_MFR_NAME: PANASONIC; ICA_PARTNUM: $$1785048$$ERJ-3GSYJ102; MFG: PANASONIC; Part Number: ERJ-12SF27R4U; RATING: 3/4W; SOURCE: DIGI P27.4ACCT-ND; TOLERANCE: 1%
R145 R159 R161 R164-R166 R168 R186 R672 R673 R675 R676 R705 R712 R718 R721 R724 R726 = R: Resistor; CCA: 143; MFG: YAGEO; Part Number: RC0402FR-0722RL; RATING: 1/16W; SOURCE: DIGI 311-22.0LRTR-ND; TOLERANCE: 1%
R125 R126 R162 R716 R717 R719 R722 R725 = R: Resistor; CCA: 68; ICA_MFR_NAME: PANASONIC; ICA_PARTNUM: $$1785048$$ERJ-3GSYJ102; MFG: PANASONIC; Part Number: ERJ-2GEJ332X; RATING: 1/10W; SOURCE: DIGI P3.3KJCT-ND; TOLERANCE: 5%
R167 = R: Resistor; CCA: 97; ICA_MFR_NAME: PANASONIC; ICA_PARTNUM: $$1785048$$ERJ-3GSYJ102; MFG: PANASONIC; Part Number: ERJ-3GEYJ223V; RATING: 1/10W; SOURCE: DIGI P22KGCT-ND; TOLERANCE: 5%
R170 = R: Resistor; CCA: 94; ICA_MFR_NAME: PANASONIC; ICA_PARTNUM: $$1785048$$ERJ-3GSYJ102; MFG: PANASONIC; Part Number: ERJ-3GEYJ152V; RATING: 1/10W; SOURCE: DIGI P1.5KGCT-ND; TOLERANCE: 5%
TP37 TP40-TP55 = Testpoint: Test point
U16 U31 = MAX3232: IC, RS-232 Line Driver/Receiver; CCA: 131; SOURCE: DIGI 296-13096-1-ND
U36 = 74LVC1G17_0: IC, Non-Inverting Schmitt-Trigger Buffer; CCA: 148; MFG: TI; Part Number: SN74LVC1G17DBVR; SOURCE: DIGI 296-11933-1-ND
U37 = 74LVC1G125_0: IC, Non-Inverting Buffer, Tri-State; CCA: 149; MFG: TI; Part Number: SN74LVC1G125DBVR; SOURCE: DIGI 296-11603-1-ND
U507 = SN65220: IC, USB Port Transient Suppressor; CCA: 152; Part Number: SN65220DBVT; SOURCE: DIGI 296-2341-2-ND
R124 R690 R692 R695 R703 R704 R706 R710 R711 R713 R740 = R: Resistor; CCA: 62; DNI: DNI; ICA_MFR_NAME: PANASONIC; ICA_PARTNUM: $$1785048$$ERJ-3GSYJ102; MFG: PANASONIC; Part Number: ERJ-2GE0R00X; RATING: 1/10W; SOURCE: DIGI P0.0JCT-ND
R702 R709 = R: Resistor; CCA: 65; DNI: DNI; ICA_MFR_NAME: PANASONIC; ICA_PARTNUM: $$1785048$$ERJ-3GSYJ102; MFG: PANASONIC; Part Number: ERJ-2GEJ103X; RATING: 1/10W; SOURCE: DIGI P10.0KLCT-ND; TOLERANCE: 5%
U34 U35 = FLASH_SPANSION: IC, Flash; CCA: 130; MFG: ISSI; Part Number: IS29GL128-70SLET
J34 J38 = JUMPER-1x3: Jumper, 1x3; CCA: 129; MFG: HARWIN; Part Number: M22-2510305; SOURCE: DIGI 952-1312-ND
J45 = 12_HEADER: Connector; CCA: 110; MFG: HIROSE; Part Number: FH12-12S-0.5SH(55); SOURCE: DIGI HFJ112TR-ND; Type: Flex
J48 = CON3: Connector, 3 pin; CCA: 19; MFG: MOLEX; Part Number: 0533980371; SOURCE: DIGI WM7607CT-ND
R140 R171-R180 R679 R680 R682 R735-R738 R744 = R: Resistor; CCA: 67; MFG: PANASONIC; Part Number: ERJ-2GEJ330X; RATING: 1/10W; SOURCE: DIGI P33JCT-ND; TOLERANCE: 5%
J36 = CON22: Connector, 2x11 pin; CCA: 26; MFG: JST; Part Number: B22B-PHDSS(LF)(SN); SOURCE: DIGI 455-1768-ND
J39 = CON12: Connector, 12 pin; CCA: 22; MFG: MOLEX; Part Number: 53398-1271; SOURCE: DIGI WM7616CT-ND
J44 = CON20A: Connector, 20 pin; CCA: 173; MFG: SAMTEC; Part Number: TSM-110-01-SM-DV; SOURCE: SAMTEC
J49 = CON6: Connector, 6 pin; CCA: 21; MFG: MOLEX; Part Number: 0533980671; SOURCE: DIGI WM7610CT-ND
RN502-RN505 = RPACK_4: Resistor Network; CCA: 108; MFG: PANASONIC; Part Number: EXB-38V103JV; RATING: 1/16W; SOURCE: DIGI Y9103CT-ND; TOLERANCE: 5%
U30 = SN74LVC1G06_0: IC, Inverter; CCA: 146; MFG: TI; Part Number: SN74LVC1G06DBVR; SOURCE: DIGI 296-8483-1-ND
U39 U508 = SN74LVC827A: IC, 10 Ch Buffer; CCA: 151; MFG: TI; Part Number: SN74LVC827APWR; SOURCE: DIGI 296-8548-1-ND
U511 U512 = SN74LVC2G125: IC, DUAL BUFFER; CCA: 150; MFG: TI; Part Number: SN74LVC2G125DCUR; SOURCE: DIGI 296-13265-2-ND
U513 = 74AUP1G79: IC, Non-inverting Flip-Flop; CCA: 145; MFG: TI; Part Number: SN74AUP1G79DBVR
R128 = R: Resistor; CCA: 64; ICA_MFR_NAME: PANASONIC; ICA_PARTNUM: $$1785048$$ERJ-3GSYJ102; MFG: PANASONIC; Part Number: ERJ-2GEJ102X; RATING: 1/10W; SOURCE: DIGI P1.0KJCT-ND; TOLERANCE: 5%
R648 R649 = R: Resistor; CCA: 67; ICA_MFR_NAME: PANASONIC; ICA_PARTNUM: $$1785048$$ERJ-3GSYJ102; MFG: PANASONIC; Part Number: ERJ-2GEJ330X; RATING: 1/10W; SOURCE: DIGI P33JCT-ND; TOLERANCE: 5%
U515 = SN74AUP1T34: IC V-LEVEL XLATR UNIDIR SC70-5; Digi-Key Part Number: 296-34900-2-ND; Manuf Part Number: SN74AUP1T34DCKR; Manufacturer: Texas Instruments; Part Number: SN74AUP1T34DCKR
C58 = CAPACITOR_POL_SM: Capacitor; CCA: 56; MFG: PANASONIC; Part Number: EEE-FK1E101P; RATING: 25V; TOLERANCE: 20%
C64 = CAP_NP: Capacitor; CCA: 37; MFG: KEMET; Part Number: C0603S681K3RACTU; RATING: 25V; SOURCE: DIGI PCC2277CT-ND; TOLERANCE: 10%; Type: X7R; VDC: 25V
C65 = CAPACITOR_POL_SM: Capacitor; CCA: 106; MFG: RUBYCON; Part Number: 25PX1000MEFCT810X16; RATING: 25V; TOLERANCE: 20%
C119 = CAP_NP: Capacitor; CCA: 119; MFG: MURATA; Part Number: GRM21BR61E106KA73L; RATING: 25V; SOURCE: DIGI 490-7207-1-ND; TOLERANCE: 10%; Type: X5R; VDC: 25V
C120 C942 C943 C954 C955 C957 = CAP_NP: Capacitor; CCA: 48; MFG: KEMET; Part Number: C0603C104K3RACTU; RATING: 25V; SOURCE: DIGI PCC2277CT-ND; TOLERANCE: 10%; Type: X7R; VDC: 25V
C121 = CAP_NP: Capacitor; CCA: 7; MFG: AVX; Part Number: 06033A100JAT2A; RATING: 25V; SOURCE: DIGI 478-7894-1-ND; TOLERANCE: 10%; Type: X7R; VDC: 25V
D15 = DIODE: Diode; CCA: 1; MFG: Diodes Inc; Part Number: 1N5819HW-7-F
J42 = CON14: Connector, 14 pin; CCA: 18; MFG: MOLEX; Part Number: 53047-1410
J43 = CON2: Connector, 2 pin 2.5mm; MFG: JST
L12 = INDUCTOR: Filter; MFG: Murata; Part Number: BLM18EG121SN1D; RATING: 2A
L17 = INDUCTOR: Inductor; CCA: 158; MFG: Bourns; Part Number: SRR1210-331M
L23 = INDUCTOR_SM: Filter; MFG: Murata; Part Number: BLM18EG121SN1D; RATING: 2A
R98 R639 = R: Resistor; CCA: 61; MFG: PANASONIC; Part Number: ERJ-2BQJR36X; RATING: 1/8W; SOURCE: DIGI P.36AKCT-ND; TOLERANCE: 1%
R99 = RESISTOR: Resistor; CCA: 90; MFG: PANASONIC; Part Number: ERJ-3EKF8201V; RATING: 1/10W; TOLERANCE: 1%
R100 = RESISTOR: Resistor; CCA: 93; MFG: PANASONIC; Part Number: ERJ-3EKF9530V; RATING: 1/10W; TOLERANCE: 1%
R182 = RESISTOR: Resistor; CCA: 88; MFG: PANASONIC; Part Number: ERJ-3EKF4702V; RATING: 1/10W; TOLERANCE: 1%
R728 = RESISTOR: Resistor; CCA: 82; MFG: PANASONIC; Part Number: ERJ-3EKF3012V; Tolerence: 1%
R729 = RESISTOR: Resistor; CCA: 72; MFG: PANASONIC; Part Number: ERJ-2RKF1002X; RATING: 1/10W; TOLERANCE: 1%; Tolerence: 1%
U17 = MC34063A_1: IC, SW ADJ INV Voltage Reg; MFG: TI; Part Number: MC34063ADR
U40 = 74LVC827A: IC, 10 Ch Buffer; CCA: 151; MFG: TI; Part Number: SN74LVC827APWR; SOURCE: DIGI 296-8548-1-ND
U41 = REF02_0: IC, VREF 5V; MFG: TI; Part Number: REF02AU/2K5
U42 = TCA0372_0: IC, OpAmp; MFG: ON Semiconductor; Part Number: TCA0372DWR2G
U43 = TLC7524C: IC, DAC 8-Bit; CCA: 162; MFG: TI; Part Number: TLC7524IPW
C90 C91 C817 C851 = CAP_NP: Capacitor; CCA: 114; MFG: KEMET; Part Number: C1206C107M9PACTU; RATING: 6.3V; SOURCE: DIGI 490-4539-1-ND; TOLERANCE: 20%; Type: X5R
C96 C103 C112 C853 C872 C873 C892 = CAP_NP: Capacitor; CCA: 112; MFG: MURATA; Part Number: GRM21BR71A106KE51L; RATING: 10V; SOURCE: DIGI 490-3905-1-ND; TOLERANCE: 10%; Type: X7R
FB3 FB504-FB509 = INDUCTOR: Ferrite; CCA: 30; ICA_MFR_NAME: STEWARD; ICA_PARTNUM: $$731362$$MI0603J680R-10; MFG: MURATA; Part Number: BLM18AG471SN1D; RATING: 500mA, 100MHz; SOURCE: DIGI 490-1013-1-ND
R640 = R: Resistor; CCA: 142; MFG: YAGEO; Part Number: RC0402FR-071RL; RATING: 1/16W; SOURCE: DIGI 311-1.00LRCT-ND; TOLERANCE: 1%

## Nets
+5VREF: U41.6(VOUT) U43.15(REF)
GND: C58.2 C59.1 C65.1 C67.2 C70.2 C90.2 C91.2 C94.2 C96.2 C97.1 C99.2 C102.2 C103.2 C108.1 C112.2 C116.1 C120.1 C790.2 C791.2 C800.2 C802.2 C803.2 C804.2 C805.2 C806.2 C817.2 C818.1 C819.1 C820.2 C822.2 C823.2 C824.2 C825.2 C826.2 C827.2 C828.2 C837.2 C839.2 C840.2 C841.2 C842.2 C847.2 C851.2 C852.2 C853.2 C855.2 C856.2 C859.2 C860.2 C862.2 C863.2 C867.2 C868.2 C872.2 C873.2 C876.2 C877.2 C881.2 C882.2 C885.2 C886.2 C889.2 C890.2 C892.2 C895.2 C896.2 C901.2 C902.2 C904.2 C905.2 C906.2 C907.2 C908.2 C909.2 C910.2 C915.2 C916.2 C917.2 C918.2 C919.2 C920.2 C921.2 C933.2 C934.2 C936.2 C937.2 C940.1 C941.1 C942.1 C943.1 C944.1 C954.1 C955.1 C956.1 C957.1 C959.1 C960.1 C963.1 C964.1 C965.2 C967.1 C968.1 J26.5(GND) J35.5(GND) J36.7 J36.10 J36.15 J36.16 J39.1 J41.4 J42.13 J42.14 J43.2 J44.1 J44.20 J45.3 J45.5 J45.7 J45.9 J45.11 J48.3 J49.6 L17.2 R96.1 R99.2 R128.2 R129.1 R130.1 R167.1 R182.2 R687.2 R688.2 R692.2 R695.2 R708.2 R715.2 R729.2 R749.1 RN502.5 RN502.6 RN502.7 RN502.8 RN503.5 RN503.6 RN503.7 RN503.8 RN505.5 RN505.6 RN505.7 RN505.8 U16.15(GND) U30.3 U31.15(GND) U33.A1(GND) U33.A2(GND) U33.A3(GND) U33.A17(L_VDQPAD_1) U33.A18(L_VDQPAD_3) U33.A24(GND) U33.A25(GND) U33.A26(GND) U33.AA6(GND) U33.AA9(GND) U33.AA12(GND) U33.AA15(GND) U33.AA18(GND) U33.AA21(GND) U33.AB5(GND) U33.AB14(VTEST1) U33.AB15(VTEST2) U33.AB16(R_VDQPAD_3) U33.AB17(R_VDQPAD_1) U33.AB22(GND) U33.AC4(GND) U33.AC17(R_VDQPAD_6) U33.AC18(R_VDQPAD_4) U33.AC23(GND) U33.AD3(GND) U33.AD17(R_VDQPAD_2) U33.AD18(R_VDQPAD_0) U33.AD24(GND) U33.AE3(GND) U33.AE17(R_VDQPAD_7) U33.AE24(GND) U33.AE25(GND) U33.AF1(GND) U33.AF2(GND) U33.AF3(GND) U33.AF17(R_VDQPAD_5) U33.AF24(GND) U33.AF25(GND) U33.AF26(GND) U33.B1(GND) U33.B2(GND) U33.B3(GND) U33.B17(L_VDQPAD_5) U33.B18(L_VDQPAD_7) U33.B25(GND) U33.C3(GND) U33.C18(L_VDQPAD_2) U33.C24(GND) U33.D4(GND) U33.D17(L_VDQPAD_0) U33.D18(L_VDQPAD_6) U33.D23(GND) U33.E5(GND) U33.E15(VTEST3) U33.E16(VTEST4) U33.E17(L_VDQPAD_4) U33.E22(GND) U33.F6(GND) U33.F9(GND) U33.F12(GND) U33.F15(GND) U33.F18(GND) U33.F21(GND) U33.G5(GND) U33.J5(GND) U33.J6(GND) U33.J21(GND) U33.K5(LVDS_AVS1) U33.K26(PLLD_VAS) U33.L5(GND) U33.L12(GND) U33.L13(GND) U33.L14(GND) U33.L15(GND) U33.L23(PLLD_VSS) U33.L25(PLLM1_VAS) U33.M6(GND) U33.M11(GND) U33.M12(GND) U33.M13(GND) U33.M14(GND) U33.M15(GND) U33.M16(GND) U33.M21(GND) U33.M22(PLLM1_VSS) U33.N5(GND) U33.N11(GND) U33.N12(GND) U33.N13(GND) U33.N14(GND) U33.N15(GND) U33.N16(GND) U33.P11(GND) U33.P12(GND) U33.P13(GND) U33.P14(GND) U33.P15(GND) U33.P16(GND) U33.P24(PLLM2_VSS) U33.R5(GND) U33.R6(GND) U33.R11(GND) U33.R12(GND) U33.R13(GND) U33.R14(GND) U33.R15(GND) U33.R16(GND) U33.R24(PLLS_VAS) U33.R26(PLLM2_VAS) U33.T12(GND) U33.T13(GND) U33.T14(GND) U33.T15(GND) U33.U5(GND) U33.V5(LVDS_AVS2) U33.V6(GND) U33.V21(GND) U33.W5(GND) U33.Y5(GND) U34.1(NC) U34.33(VSS) U34.52(VSS) U34.56(NC) U35.1(NC) U35.33(VSS) U35.52(VSS) U35.56(NC) U36.1(~{OE}) U36.3(GND) U37.3(GND) U39.1(~{OE1}) U39.12(GND) U39.13(~{OE2}) U40.1(OE1) U40.12(GND) U40.13(OE2) U41.4(GND) U42.8(B_IN_+) U43.2(OUT2) U43.3(GND) U43.12(CSZ) U507.2(GND1) U507.5(GND2) U508.1(~{OE1}) U508.9(A8) U508.10(A9) U508.12(GND) U508.13(~{OE2}) U511.1(1OEz) U511.4(GND) U511.7(2OEz) U512.1(1OEz) U512.4(GND) U512.7(2OEz) U513.3(GND) U515.3(GND) ; also on sheet 2 5 6 7 8 9 10 11 12 13 14 15 16 17 18 19 28 30 31 32 33 35 36
P5V_M: C954.2 C959.2 J45.1 U43.14(VDD) ; also on sheet 13 16 17 30
P12V: C942.2 C955.2 J36.2 J42.1 J42.2 L12.2 U41.2(VIN) U42.1(VCC) ; also on sheet 2 8 9 12 13 14 15 16 33
3D_TOGGLE: U508.8(A7) ; also on sheet 16 17
A1P8V_M: R640.1 ; also on sheet 13
A_BLU_PWM: J36.5 J44.7 U39.21(Y3)
A_GRN_PWM: J36.3 J44.5 U39.22(Y2)
A_LED4_PWM: J36.9 J44.2 U39.20(Y4)
A_LED5_PWM: J36.11 J44.4 U39.19(Y5)
A_LED6_PWM: J36.13 J44.6 U39.18(Y6)
A_LED7_PWM: J36.17 J44.11 U39.17(Y7)
A_LED8_PWM: J36.19 J44.13 U39.16(Y8)
A_RED_PWM: J36.1 J44.3 U39.23(Y1)
A_SPARE_1: J36.18 J39.2 U508.23(Y1)
A_SPARE_2: J36.22 U39.15(Y9)
A_SPARE_3: J36.20 U39.14(Y10)
A_SSP0_CLK: R159.1 R161.1 R164.1 R165.1 TP43.1 U33.AD4(SSP0_CLK)
A_SSP0_TXD: R166.1 R168.1 TP45.1 U33.AB7(SSP0_TXD)
ACT_SYNC_0: U32.AC11(GPIO_51) ; also on sheet 33
ACT_SYNC_1: U32.AB12(GPIO_52) ; also on sheet 33
ACT_SYNC_3: R749.2 U32.C25(GPIO_25) U515.2(A)
ADC_CSZ: J45.10 R682.1 TP55.1
ADC_RST: J45.2 R679.1 TP53.1
ADC_SCLK: J45.4 R140.1 TP48.1
ADC_SDIN: J45.6 TP54.1 U33.AE10(GPIO_74)
ADC_SDO: J38.1 J45.8 TP49.1
BLU_LED_EN: RN505.3 U508.7(A6) ; also on sheet 17
BLU_PWM: RN503.2 U33.C20(GPIO_06) U39.4(A3)
CLK: R171.1 U40.23(Y1) U43.13(WRZ)
CW_INDEX1: U32.G22(GPIO_37) ; also on sheet 12 16
D0: R172.1 U40.22(Y2) U43.11(D0)
D1: R173.1 U40.21(Y3) U43.10(D1)
D2: R174.1 U40.20(Y4) U43.9(D2)
D3: R175.1 U40.19(Y5) U43.8(D3)
D4: R176.1 U40.18(Y6) U43.7(D4)
D5: R177.1 U40.17(Y7) U43.6(D5)
D6: R178.1 U40.16(Y8) U43.5(D6)
D7: R179.1 U40.15(Y9) U43.4(D7)
DASYNC: U32.R22(GPIO_41) ; also on sheet 17
DB/RED_PWM: RN505.4 U39.2(A1) ; also on sheet 16 17
DRV_RST: U511.5(2A) ; also on sheet 17
FLASH_A19_A21: R706.2 R707.2 U35.11(A19)
FLASH_A21_VPP: R694.2 R704.1 U35.15(A21)
FLASH_CSSZ: R672.2 U35.32(CE#)
FLASH_CSZ: R672.1 U33.E12(PM_CSZ_1)
FLASH_RSTZ: R690.1 R691.1 U34.14(RESET#) U35.14(RESET#)
FREQ_SENSOR: J38.3 J48.2
GPIO_21: RN504.3 U33.E20(GPIO_21) U39.10(A9)
GPIO_23: RN504.4 U33.E21(GPIO_23) U39.11(A10)
GPIO_54: RN502.4 U508.2(A1) ; also on sheet 17
GPIO_75: J38.2 R680.1
GRN_LED_EN: RN505.2 U508.6(A5) ; also on sheet 17
GRN_PWM: RN503.1 U33.B20(GPIO_05) U39.3(A2)
HBT_CLK_OUT: U32.U24(GPIO_44) ; also on sheet 17
HBT_CLKIN_0: R648.1 ; also on sheet 17
HBT_DI_0: R649.1 ; also on sheet 17
HBT_DO: U32.U25(GPIO_43) ; also on sheet 17
HOLD_BOOTZ: U32.F24(GPIO_39) ; also on sheet 17
LAMPLITZ: J39.4 ; also on sheet 17
LED4_PWM: RN503.3 U33.A20(GPIO_07) U39.5(A4)
LED5_PWM: RN503.4 U33.A21(GPIO_08) U39.6(A5)
LED6_PWM: RN502.1 U33.B21(GPIO_09) U39.7(A6)
LED7_PWM: RN502.2 U33.A22(GPIO_10) U39.8(A7)
LED8_PWM: RN502.3 U33.A23(GPIO_11) U39.9(A8)
LED_DIN: J49.2 R734.2 R740.1 TP47.1
LED_DIR: J49.5 R737.2 TP52.1
LED_DOUT: J49.3 R744.2 TP50.1
LED_EN: J34.2 J39.3
LED_OE: J49.4 R738.2 TP51.1
LED_SCLK: J49.1 R736.2 TP46.1
LMPCTRL: U508.3(A2) ; also on sheet 17
LMPSTAT: U32.AF8(LMPSTAT) ; also on sheet 17
P1P1V_M: C96.1 C817.1 C822.1 C824.1 C826.1 C828.1 C837.1 C840.1 C847.1 C855.1 C860.1 C862.1 C863.1 C867.1 C877.1 C881.1 C882.1 C885.1 C890.1 C892.1 C895.1 C902.1 C904.1 C906.1 C907.1 C908.1 C910.1 R639.1 U33.AA8(VDDC) U33.AA11(VDDC) U33.AA14(VDDC) U33.AA17(VDDC) U33.AA20(VDDC) U33.F7(VDDC) U33.F10(VDDC) U33.F13(VDDC) U33.F16(VDDC) U33.F19(VDDC) U33.G21(VDDC) U33.H6(VDDC) U33.K21(VDDC) U33.L6(VDDC) U33.L11(VDDC) U33.L16(VDDC) U33.N21(VDDC) U33.P6(VDDC) U33.T11(VDDC) U33.T16(VDDC) U33.T21(VDDC) U33.U6(VDDC) U33.W21(VDDC) U33.Y6(VDDC) ; also on sheet 13
P1P5V: C968.2 U515.5(VCCB) ; also on sheet 5 6 8 9 32 33
P1P8V_M: C112.1 C823.1 C827.1 C842.1 C851.1 C853.1 C868.1 C876.1 C905.1 C909.1 C915.1 C916.1 C917.1 C918.1 C919.1 C920.1 C921.1 C933.1 C934.1 C936.1 C937.1 U33.AA5(LVDSAVD) U33.AA13(DRAMVDD) U33.AE1(LVDSAVD) U33.C1(LVDSAVD) U33.F5(LVDSAVD) U33.F14(DRAMVDD) U33.G6(LVDSAVD) U33.H5(DRAMVDD) U33.H21(DRAMVDD) U33.K6(LVDSAVD) U33.M5(LVDSAVD) U33.N6(DRAMVDD) U33.P5(LVDSAVD) U33.P21(DRAMVDD) U33.T5(LVDSAVD) U33.T6(DRAMVDD) U33.U21(DRAMVDD) U33.W6(LVDSAVD) ; also on sheet 13
P3P3V: C967.2 U515.1(VCCA) ; also on sheet 7 9 30 31 33
P3P3V_M: C59.2 C103.1 C108.2 C116.2 C818.2 C820.1 C825.1 C839.1 C841.1 C852.1 C856.1 C859.1 C872.1 C873.1 C886.1 C889.1 C896.1 C901.1 C944.2 C956.2 C960.2 C963.2 C964.2 C965.1 DN9.3 J48.1 R97.2 R136.2 R162.2 R668.1 R671.1 R693.1 R702.1 R704.2 R716.2 R717.2 R719.2 R722.2 R725.2 RN504.5 RN504.6 RN504.7 RN504.8 U16.16(VCC) U30.5 U33.AA7(VDD33) U33.AA10(VDD33) U33.AA16(VDD33) U33.AA19(VDD33) U33.AE26(CFO_VDD33) U33.F8(VDD33) U33.F11(VDD33) U33.F17(VDD33) U33.F20(VDD33) U33.L21(VDD33) U33.R21(VDD33) U33.Y21(VDD33) U35.43(VCC) U36.5(VCC) U37.5(VCC) U39.24(VCC) U508.24(VCC) U511.8(Vcc) U512.8(Vcc) U513.5(VCC) ; also on sheet 12 13 14 15 16 17 18 30 35
P3P3V_S: C97.2 C819.2 C941.2 R125.2 R126.2 R131.2 R669.1 R674.1 R696.1 R709.1 R711.2 U31.16(VCC) U34.43(VCC) U40.24(VCC) ; also on sheet 12 14 15 19 28
P-12V: C64.1 C65.2 C943.2 C957.2 D15.2(A) R100.2 U17.4(GND) U42.4(VEE1) U42.5(VEE2) U42.12(VEE4) U42.13(VEE3)
PLLD_VAD: C803.1 FB507.2 U33.K25(PLLD_VAD)
PLLD_VDD: C804.1 FB505.2 U33.L22(PLLD_VDD)
PLLM1_VAD: C800.1 FB506.2 U33.L24(PLLM1_VAD)
PLLM1_VDD: C94.1 FB3.2 U33.L26(PLLM1_VDD)
PLLM2_VAD: C805.1 FB509.2 U33.R25(PLLM2_VAD)
PLLM2_VDD: C802.1 FB504.2 U33.P23(PLLM2_VDD)
PLLS_VAD: C806.1 FB508.2 U33.R23(PLLS_VAD)
PM_ADR_0: U33.C7(PM_ADDR_00) U35.31(A0)
PM_ADR_1: U33.A7(PM_ADDR_01) U35.26(A1)
PM_ADR_2: U33.B7(PM_ADDR_02) U35.25(A2)
PM_ADR_3: U33.C8(PM_ADDR_03) U35.24(A3)
PM_ADR_4: U33.D8(PM_ADDR_04) U35.23(A4)
PM_ADR_5: U33.A8(PM_ADDR_05) U35.22(A5)
PM_ADR_6: U33.B8(PM_ADDR_06) U35.21(A6)
PM_ADR_7: U33.C9(PM_ADDR_07) U35.20(A7)
PM_ADR_8: U33.D9(PM_ADDR_08) U35.10(A8)
PM_ADR_9: U33.E9(PM_ADDR_09) U35.9(A9)
PM_ADR_10: U33.A9(PM_ADDR_10) U35.8(A10)
PM_ADR_11: U33.B9(PM_ADDR_11) U35.7(A11)
PM_ADR_12: U33.C10(PM_ADDR_12) U35.6(A12)
PM_ADR_13: U33.D10(PM_ADDR_13) U35.5(A13)
PM_ADR_14: U33.E10(PM_ADDR_14) U35.4(A14)
PM_ADR_15: U33.C11(PM_ADDR_15) U35.3(A15)
PM_ADR_16: U33.D11(PM_ADDR_16) U35.54(A16)
PM_ADR_17: U33.A11(PM_ADDR_17) U35.19(A17)
PM_ADR_18: U33.B11(PM_ADDR_18) U35.18(A18)
PM_ADR_19: R703.1 R707.1 U33.C12(PM_ADDR_19)
PM_ADR_20: U33.D12(PM_ADDR_20) U35.12(A20)
PM_ADR_21: R688.1 R694.1 R706.1 U33.E11(GPIO_35)
PM_ADR_22: R708.1 U33.A12(GPIO_36) U35.2(A22)
PM_DAT_0: U33.B13(PM_DATA_00) U35.35(DQ0)
PM_DAT_1: U33.C14(PM_DATA_01) U35.37(DQ1)
PM_DAT_2: U33.D14(PM_DATA_02) U35.39(DQ2)
PM_DAT_3: U33.E13(PM_DATA_03) U35.41(DQ3)
PM_DAT_4: U33.A14(PM_DATA_04) U35.44(DQ4)
PM_DAT_5: U33.B14(PM_DATA_05) U35.46(DQ5)
PM_DAT_6: U33.C15(PM_DATA_06) U35.48(DQ6)
PM_DAT_7: U33.D15(PM_DATA_07) U35.50(DQ7)
PM_DAT_8: U33.E14(PM_DATA_08) U35.36(DQ8)
PM_DAT_9: U33.C16(PM_DATA_09) U35.38(DQ9)
PM_DAT_10: U33.D16(PM_DATA_10) U35.40(DQ10)
PM_DAT_11: U33.B15(PM_DATA_11) U35.42(DQ11)
PM_DAT_12: U33.A15(PM_DATA_12) U35.45(DQ12)
PM_DAT_13: U33.A16(PM_DATA_13) U35.47(DQ13)
PM_DAT_14: U33.B16(PM_DATA_14) U35.49(DQ14)
PM_DAT_15: U33.C17(PM_DATA_15) U35.51(DQ15)
PM_OESZ: R673.2 U35.34(OE#)
PM_OEZ: R673.1 U33.C13(PM_OEZ)
PM_WESZ: R705.2 U35.13(WE#)
PM_WEZ: R705.1 U33.B12(PM_WEZ)
POSENSE: R691.2 ; also on sheet 12
PWRGOOD: R690.2 ; also on sheet 12 18 30
RED_LED_EN: RN505.1 U508.5(A4) ; also on sheet 17
S_FLASH_A19_A21: R713.2 R714.2 U34.11(A19)
S_FLASH_A21_VPP: R697.2 R711.1 U34.15(A21)
S_FLASH_CSSZ: R675.2 U34.32(CE#)
S_FLASH_CSZ: R675.1 U32.E12(PM_CSZ_1)
S_PM_ADR_0: U32.C7(PM_ADDR_00) U34.31(A0)
S_PM_ADR_1: U32.A7(PM_ADDR_01) U34.26(A1)
S_PM_ADR_2: U32.B7(PM_ADDR_02) U34.25(A2)
S_PM_ADR_3: U32.C8(PM_ADDR_03) U34.24(A3)
S_PM_ADR_4: U32.D8(PM_ADDR_04) U34.23(A4)
S_PM_ADR_5: U32.A8(PM_ADDR_05) U34.22(A5)
S_PM_ADR_6: U32.B8(PM_ADDR_06) U34.21(A6)
S_PM_ADR_7: U32.C9(PM_ADDR_07) U34.20(A7)
S_PM_ADR_8: U32.D9(PM_ADDR_08) U34.10(A8)
S_PM_ADR_9: U32.E9(PM_ADDR_09) U34.9(A9)
S_PM_ADR_10: U32.A9(PM_ADDR_10) U34.8(A10)
S_PM_ADR_11: U32.B9(PM_ADDR_11) U34.7(A11)
S_PM_ADR_12: U32.C10(PM_ADDR_12) U34.6(A12)
S_PM_ADR_13: U32.D10(PM_ADDR_13) U34.5(A13)
S_PM_ADR_14: U32.E10(PM_ADDR_14) U34.4(A14)
S_PM_ADR_15: U32.C11(PM_ADDR_15) U34.3(A15)
S_PM_ADR_16: U32.D11(PM_ADDR_16) U34.54(A16)
S_PM_ADR_17: U32.A11(PM_ADDR_17) U34.19(A17)
S_PM_ADR_18: U32.B11(PM_ADDR_18) U34.18(A18)
S_PM_ADR_19: R710.1 R714.1 U32.C12(PM_ADDR_19)
S_PM_ADR_20: U32.D12(PM_ADDR_20) U34.12(A20)
S_PM_ADR_21: R687.1 R697.1 R713.1 U32.E11(GPIO_35)
S_PM_ADR_22: R715.1 U32.A12(GPIO_36) U34.2(A22)
S_PM_DAT_0: U32.B13(PM_DATA_00) U34.35(DQ0)
S_PM_DAT_1: U32.C14(PM_DATA_01) U34.37(DQ1)
S_PM_DAT_2: U32.D14(PM_DATA_02) U34.39(DQ2)
S_PM_DAT_3: U32.E13(PM_DATA_03) U34.41(DQ3)
S_PM_DAT_4: U32.A14(PM_DATA_04) U34.44(DQ4)
S_PM_DAT_5: U32.B14(PM_DATA_05) U34.46(DQ5)
S_PM_DAT_6: U32.C15(PM_DATA_06) U34.48(DQ6)
S_PM_DAT_7: U32.D15(PM_DATA_07) U34.50(DQ7)
S_PM_DAT_8: U32.E14(PM_DATA_08) U34.36(DQ8)
S_PM_DAT_9: U32.C16(PM_DATA_09) U34.38(DQ9)
S_PM_DAT_10: U32.D16(PM_DATA_10) U34.40(DQ10)
S_PM_DAT_11: U32.B15(PM_DATA_11) U34.42(DQ11)
S_PM_DAT_12: U32.A15(PM_DATA_12) U34.45(DQ12)
S_PM_DAT_13: U32.A16(PM_DATA_13) U34.47(DQ13)
S_PM_DAT_14: U32.B16(PM_DATA_14) U34.49(DQ14)
S_PM_DAT_15: U32.C17(PM_DATA_15) U34.51(DQ15)
S_PM_OESZ: R676.2 U34.34(OE#)
S_PM_OEZ: R676.1 U32.C13(PM_OEZ)
S_PM_WESZ: R712.2 U34.13(WE#)
S_PM_WEZ: R712.1 U32.B12(PM_WEZ)
S_SSP2_CLK: U32.K23(GPIO_71) ; also on sheet 12
S_SSP2_CSZ0: R125.1 U32.J26(GPIO_69) ; also on sheet 12
S_SSP2_DI: R126.1 U32.K24(GPIO_72) ; also on sheet 12
S_SSP2_DO: U32.J25(GPIO_68) ; also on sheet 12
S_UART0_CTSZ: U31.12(R1OUT) U32.AE2(UART0_CTSZ)
S_UART0_CTSZ_CON: J35.7(RTS) U31.13(R1IN)
S_UART0_DCD_CON: J35.1(DCD) R139.1
S_UART0_DSR_CON: J35.6(DSR) R138.2 R139.2
S_UART0_DTR_CON: J35.4(DTR) R138.1
S_UART0_RSTZ_CON: J35.8(CTS) U31.14(T1OUT)
S_UART0_RTSZ: R130.2 U31.11(T1IN) U32.AD2(UART0_RTSZ)
S_UART0_RXD: U31.9(R2OUT) U32.AD1(UART0_RXD)
S_UART0_RXD_CON: J35.3(TD) U31.8(R2IN)
S_UART0_TXD: R131.1 U31.10(T2IN) U32.AB3(UART0_TXD)
S_UART0_TXD_CON: J35.2(RD) U31.7(T2OUT)
SCL1: U32.A10(IIC0_SCL) ; also on sheet 16 17 30 33 35
SDA1: U32.B10(IIC0_SDA) ; also on sheet 16 17 30 33 35
SENSE_PULSE: RN504.1 U33.G25(GPIO_58) U508.11(A10)
SENSE_PULSE_BUF: J36.12 J39.12 J44.8 U508.14(Y10)
SLAVE: R128.1 U32.V26(GPIO_47)
SLAVE_INT: R129.2 U32.V25(GPIO_48) ; also on sheet 17
SP_CLK: J42.3 R171.2
SP_D0: J42.4 R172.2
SP_D1: J42.5 R173.2
SP_D2: J42.6 R174.2
SP_D3: J42.7 R175.2
SP_D4: J42.8 R176.2
SP_D5: J42.9 R177.2
SP_D6: J42.10 R178.2
SP_D7: J42.11 R179.2
SP_FB: J42.12 R180.2
SP_STAT_IN: R124.2 U40.14(Y10)
SP_WAVE_CLK: U32.G26(GPIO_59) U40.2(A1)
SP_WAVE_D0: U32.H22(GPIO_60) U40.3(A2)
SP_WAVE_D1: U32.H23(GPIO_61) U40.4(A3)
SP_WAVE_D2: R123.2 U40.5(A4)
SP_WAVE_D3: U32.H25(GPIO_63) U40.6(A5)
SP_WAVE_D4: U32.H26(GPIO_64) U40.7(A6)
SP_WAVE_D5: U32.J22(GPIO_65) U40.8(A7)
SP_WAVE_D6: U32.J23(GPIO_66) U40.9(A8)
SP_WAVE_D7: U32.J24(GPIO_67) U40.10(A9)
SSI_3D_TOGGLE: J36.14 J39.9 J44.15 U508.17(Y7)
SSI_STB_B: J36.8 J39.8 J44.14 U508.18(Y6)
SSI_STB_G: J36.6 J39.7 J44.12 U508.19(Y5)
SSI_STB_R: J36.4 J39.6 J44.10 U508.20(Y4)
SSI_SUBFRAME: J36.21 J39.5 J44.9 U508.21(Y3)
SSP0_CLK_DMD: R165.2 ; also on sheet 2
SSP0_CLK_PMD1: R159.2 ; also on sheet 12
SSP0_CLK_PMD2: R161.2 ; also on sheet 12
SSP0_CLK_SLAVE: U32.AD4(SSP0_CLK) U36.4(O)
SSP0_CSZ0: R719.1 R721.1 TP37.1 U33.AC5(SSP0_CSZ_0)
SSP0_CSZ0_DAD1: R721.2 ; also on sheet 2
SSP0_CSZ1: R717.1 R718.1 TP40.1 U33.AB6(SSP0_CSZ_1)
SSP0_CSZ1_DMD: R718.2 ; also on sheet 2
SSP0_CSZ2: R722.1 R724.1 TP42.1 U33.AC3(SSP0_CSZ_2)
SSP0_CSZ2_PMD1: R724.2 ; also on sheet 12
SSP0_CSZ3: R725.1 R726.1 TP44.1 U33.AB4(GPIO_27)
SSP0_CSZ3_PMD2: R726.2 ; also on sheet 12
SSP0_CSZ4_SLAVE: U32.U26(GPIO_42) ; also on sheet 17
SSP0_RXD: R145.2 R716.1 TP41.1 U33.AD5(SSP0_RXD) ; also on sheet 2 11 12
SSP0_TXD: R166.2 U32.AD5(SSP0_RXD) ; also on sheet 12
SSP0_TXD_DMD: R168.2 ; also on sheet 2
SSP2/LED_DIN: R734.1 U513.1(D)
SSP2_CLK: U512.2(1A) ; also on sheet 17
SSP2_CSZ_0: U511.2(1A) ; also on sheet 17
SSP2_DIN: R739.1 R740.2 ; also on sheet 17
SSP2_DO: U512.5(2A) ; also on sheet 17
SUBFRAME: RN504.2 U33.D22(GPIO_22) U508.4(A3)
TEST_4A_AF7: U32.B26(GPIO_24) ; also on sheet 33
TEST_4B_AD8: U515.4(B) ; also on sheet 33
UART0_CTSZ: U16.12(R1OUT) U33.AE2(UART0_CTSZ)
UART0_CTSZ_CON: J26.7(RTS) U16.13(R1IN)
UART0_DCD_CON: J26.1(DCD) R103.1
UART0_DSR_CON: J26.6(DSR) R102.2 R103.2
UART0_DTR_CON: J26.4(DTR) R102.1
UART0_RSTZ_CON: J26.8(CTS) U16.14(T1OUT)
UART0_RTSZ: R96.2 U16.11(T1IN) U33.AD2(UART0_RTSZ)
UART0_RXD: U16.9(R2OUT) U33.AD1(UART0_RXD)
UART0_RXD_CON: J26.3(TD) U16.8(R2IN)
UART0_TXD: R97.1 U16.10(T2IN) U33.AB3(UART0_TXD)
UART0_TXD_CON: J26.2(RD) U16.7(T2OUT)
USB_DAT_N: R154.2 R155.1 U507.4(B)
USB_DAT_NS: DN9.1 R155.2 U33.C5(USB_DAT_N)
USB_DAT_P: R146.1 R147.2 R170.1 U507.6(A)
USB_DAT_PS: DN9.2 R146.2 U33.D6(USB_DAT_P)
USB_ENZ: R162.1 U37.1(~{OE}) ; also on sheet 17
N16906259: J41.2 R154.1
N16906499: C67.1 U16.2(V+)
N16906505: R158.2 R167.2 U37.2(I)
N16906696: C70.1 U16.6(V-)
N16906819: C68.2 U16.1(C1+)
N16906911: C68.1 U16.3(C1-)
N16906987: R170.2 U37.4(O)
N16907071: J41.1 R158.1
N16907106: C69.2 U16.4(C2+)
N16907153: J41.3 R147.1
N16907207: C69.1 U16.5(C2-)
N16910878: R668.2 U35.53(BYTE#)
N16910921: R692.1 R693.2 U35.16(WP#/ACC)
N16911179: R671.2 U35.29(VIO)
N16911537: R702.2 U35.27(NC)
N16912987: R703.2 U35.17(RY/BY#)
N17126992: R682.2 U33.AC10(GPIO_76)
N17126998: R140.2 U33.AF10(GPIO_73)
N17172867: R680.2 U33.AD10(GPIO_75)
N17223452: C91.1 C790.1 FB3.1 FB504.1 FB505.1 FB508.1 R639.2
N17234365: C90.1 C791.1 FB506.1 FB507.1 FB509.1 R640.2
N17385870: R679.2 U33.AB11(GPIO_77)
N17418052: R738.1 U511.6(1Y)
N17418070: R744.1 U512.3(2Y)
N17418086: J34.3 U30.2 U508.22(Y2)
N17423586: J34.1 R136.1 U30.4
N18080162: R669.2 U34.53(BYTE#)
N18080205: R695.1 R696.2 U34.16(WP#/ACC)
N18080461: R674.2 U34.29(VIO)
N18080682: R709.2 U34.27(NC)
N18081963: R710.2 U34.17(RY/BY#)
N18151551: R648.2 U32.V23(GPIO_50)
N18151552: R649.2 U32.V24(GPIO_49)
N18407471: R735.1 R736.1 U512.6(1Y)
N18407477: R735.2 U513.2(CLK)
N18407497: R737.1 U511.3(2Y)
N18478792: R123.1 R124.1 U32.H24(GPIO_62)
N18482740: R180.1 U40.11(A10)
N18483780: C119.1 C121.2 U42.2(B_OUT) U43.16(RFB)
N18483782: C121.1 U42.7(B_IN_-) U43.1(OUT1)
N18483788: C119.2 R182.1 U42.9(A_IN_+)
N18483809: L23.2 R186.2 R728.1 U42.16(A_OUT)
N18483811: R728.2 R729.1 U42.10(A_IN_-)
N18484372: R145.1 U32.AB7(SSP0_TXD)
N18485561: R98.1 U17.1(SWC) U17.7(IPK) U17.8(DC)
N18485563: C58.1 L12.1 R98.2 U17.6(VCC)
N18485583: R99.1 R100.1 U17.5(CII)
N18485597: C64.2 U17.3(TC)
N18485601: D15.1(K) L17.1 U17.2(SWE)
N18486599: C120.2 R186.1
N18486613: J43.1 L23.1
N18704390: C99.1 U31.2(V+)
N18704434: C102.1 U31.6(V-)
N18704438: C100.2 U31.1(C1+)
N18704442: C100.1 U31.3(C1-)
N18704468: C101.2 U31.4(C2+)
N18704479: C101.1 U31.5(C2-)
N20787727: C940.2 R164.2 U36.2(I)
N20825603: R739.2 U513.4(Q)

Not connected (* = marked no-connect by the designer): J26 9(RING)*; J35 9(RING); J39 10* 11*; J44 16* 17* 18* 19*; J45 12*; U30 1*; U32 A6(PM_BLSZ_0)* A13(PM_CSZ_2)* A19(GPIO_03)* AB4(GPIO_27)* AB6(SSP0_CSZ_1)* AC3(SSP0_CSZ_2)* AC5(SSP0_CSZ_0)* AC9(LMPCTRL)* B6(PM_BLSZ_1)* B19(GPIO_04) B22(GPIO_12)* B24(GPIO_18)* C5(USB_DAT_N)* C19(GPIO_00)* C21(GPIO_13)* C23(GPIO_20)* C26(GPIO_28)* D6(USB_DAT_P)* D13(PM_CSZ_0)* D19(GPIO_01)* D20(GPIO_14)* D21(GPIO_19)* D24(GPIO_26)* E3(GPIO_82)* E18(GPIO_02)* E19(GPIO_15)* E23(GPIO_29)* E25(GPIO_38)* E26(GPIO_53)* F26(GPIO_54)* G24(GPIO_56)* K22(GPIO_70) T22(GPIO_46)* T23(GPIO_40)* U23(GPIO_45)*; U33 A6(PM_BLSZ_0)* A13(PM_CSZ_2)* B6(PM_BLSZ_1)* D13(PM_CSZ_0)*; U34 28(NC)* 30(NC)* 55(NC)*; U35 28(NC)* 30(NC)* 55(NC)*; U507 1(NC1)* 3(NC3)*; U508 15(Y9)* 16(Y8)*

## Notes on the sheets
sheet 20
- RS - 232 PORT 0
- (signal at PC)
- Note: TI recommends signal intergrity
  analysis be performed for the SPI bus to
  determine the optimum buffering and
  termination.
- Note: This buffer prevents the USB host
  from detecting the slave device before
  ARM processor initialization.
- USB type-B jack
- Primary
- 3
- SOT-23
- 1
- 2
- Primary Controller RS-232, Synchronous Serial Port, and USB
- (C) COPYRIGHT 2023
         Texas Instruments
        All Rights Reserved
sheet 21
- Note:
  TI reference design supports both
  TSOPII-48 and TSOPII-56 Flash types.
  The reference design uses a TSOPII-48
  Flash part. Please refer to diagram
  below for pinout and footprint
  comparison.
- 1
- 56
- 2
- 55
- 3
- 1
- 48
- 54
- 4
- 2
- 47
- 53
- 5
- 3
- 46
- 52
- 6
- 7
- 4
- 5
- 44
- 45
- 50
- 51
- 8
- 6
- 43
- 49
- 9
- 7
- 42
- 48
- 10
- 8
- 41
- 47
- 11
- 9
- 40
- 46
- 12
- 13
- 10
- 11
- 38
- 39
- 44
- 45
- 14
- 12
- 37
- 43
- 15
- 13
- 36
- 42
- 16
- 14
- 35
- 41
- 17
- 15
- 34
- 40
- 18
- 16
- 33
- 39
- 19
- 20
- 17
- 18
- 31
- 32
- 37
- 38
- 21
- 19
- 30
- 36
- 22
- 20
- 29
- 35
- 23
- 21
- 28
- 34
- 24
- 22
- 27
- 33
- 25
- 26
- 23
- 24
- 25
- 26
- 31
- 32
- 27
- TSOPII-48
- 30
- 28
- 29
- TSOPII-56
- Primary
- DO NOT INSTALL
- Primary Controller Flash Memory Interface
- (C) COPYRIGHT 2023
         Texas Instruments
        All Rights Reserved
sheet 22
- Note:
  TI reference design supports both
  TSOPII-48 and TSOPII-56 Flash types.
  The reference design uses a TSOPII-48
  Flash part. Please refer to diagram
  below for pinout and footprint
  comparison.
- 1
- 2
- 55
- 56
- 3
- 1
- 48
- 54
- 4
- 2
- 47
- 53
- 5
- 3
- 46
- 52
- 6
- 4
- 45
- 51
- 7
- 5
- 44
- 50
- 8
- 9
- 6
- 7
- 42
- 43
- 48
- 49
- 10
- 8
- 41
- 47
- 11
- 9
- 40
- 46
- 12
- 10
- 39
- 45
- 13
- 11
- 38
- 44
- 14
- 15
- 12
- 13
- 36
- 37
- 42
- 43
- 16
- 14
- 35
- 41
- 17
- 15
- 34
- 40
- 18
- 16
- 33
- 39
- 19
- 17
- 32
- 38
- 20
- 18
- 31
- 37
- 21
- 22
- 19
- 20
- 29
- 30
- 35
- 36
- 23
- 21
- 28
- 34
- 24
- 22
- 27
- 33
- 25
- 23
- 26
- 32
- 26
- 24
- 25
- 31
- 27
- 28
- TSOPII-48
- 29
- 30
- TSOPII-56
- Secondary
- Secondary Controller Flash Memory Interface
- (C) COPYRIGHT 2023
         Texas Instruments
        All Rights Reserved
sheet 23
- Primary
- ADC INTEGRATING SENSOR BOARD I/F
- LIGHT TO FREQUENCY SENSOR I/F
- Primary Controller SSI Sensor Interface
- (C) COPYRIGHT 2023
         Texas Instruments
        All Rights Reserved
sheet 24
- SPI DRIVER AND CONTROL I/F
- PULL-UP/PULL-DOWN RESISTORS
- Note: U529 is needed to
  read from an OSRAM  driver
- PWM SSI DRIVER I/F
- TESTPOINTS
- SSI Driver Interfaces
- (C) COPYRIGHT 2023
         Texas Instruments
        All Rights Reserved
sheet 25
- Secondary RS - 232 PORT 0
- (signal at PC)
- Secondary
- Secondary
- Secondary Controller GPIO and Smooth Picture I/F
- (C) COPYRIGHT 2023
         Texas Instruments
        All Rights Reserved
sheet 26
- -12V Reg
- +5V REF
- OUTPUT
- Actuator I/F
- (C) COPYRIGHT 2023
         Texas Instruments
        All Rights Reserved
sheet 27
- DLPC4420 P1P1V Bypass Capacitors
- DLPC4420 P1P8V LVDS Bypass Capacitors
- DLPC4420 P1P8V DRAM Bypass Capacitors
- DLPC4420 P3P3V Bypass Capacitors
- Primary
- Primary Controller Power and Bypass Capacitors
- (C) COPYRIGHT 2023
         Texas Instruments
        All Rights Reserved
